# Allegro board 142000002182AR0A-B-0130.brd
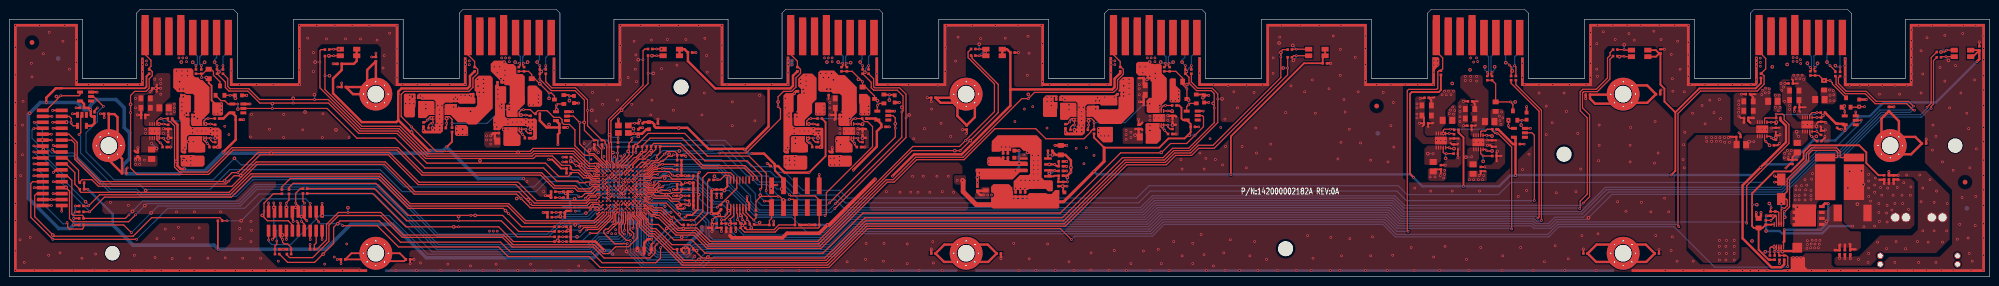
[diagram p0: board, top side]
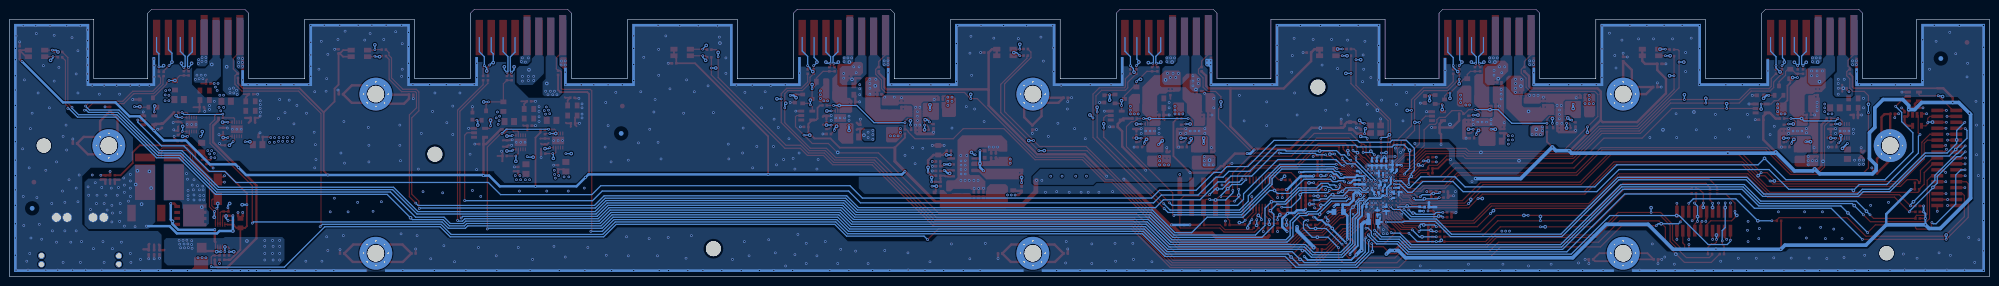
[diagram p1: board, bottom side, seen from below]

Outline 422.69 x 57.11 mm; copper layers: TOP, G2, V3, BOTTOM. Coordinates in mm from the lower left corner of the outline.
Outline path: 0,55 0,0 ; 0,55 15.6,55 ; 0,55 0,0 ; 0,55 15.6,55 ; 0,0 422.69,0 ; 0,0 422.69,0 ; 15.6,55 15.6,42.3 ; 15.6,55 15.6,42.3 ; 422.69,0 422.69,55 ; 422.69,0 422.69,55 ; 15.6,42.3 27.12,42.3 ; 15.6,42.3 27.12,42.3 ; 27.12,42.3 27.12,56.31 ; 27.12,42.3 27.12,56.31 ; 27.12,56.31 27.92,57.11 47.83,57.11 48.63,56.31 ; 48.63,56.31 48.63,42.3 ; 48.63,56.31 48.63,42.3 ; 48.63,42.3 60.61,42.3 ; 48.63,42.3 60.61,42.3 ; 60.61,42.3 60.61,55 ; 60.61,42.3 60.61,55 ; 60.61,55 84.04,55 ; 60.61,55 84.04,55 ; 84.04,55 84.04,42.3 ; 84.04,55 84.04,42.3 ; 84.04,42.3 96.02,42.3 ; 84.04,42.3 96.02,42.3 ; 96.02,42.3 96.02,56.31 ; 96.02,42.3 96.02,56.31 ; 96.02,56.31 96.82,57.11 116.73,57.11 117.53,56.31 ; 117.53,56.31 117.53,42.3 ; 117.53,56.31 117.53,42.3 ; 117.53,42.3 129.05,42.3 ; 117.53,42.3 129.05,42.3 ; 129.05,42.3 129.05,55 ; 129.05,42.3 129.05,55 ; 129.05,55 153.4,55 ; 129.05,55 153.4,55 ; 153.4,55 153.4,42.3 ; 153.4,55 153.4,42.3 ; 153.4,42.3 164.92,42.3 ; 153.4,42.3 164.92,42.3 ; 164.92,42.3 164.92,56.31 ; 164.92,42.3 164.92,56.31 ; 164.92,56.31 165.72,57.11 185.63,57.11 186.43,56.31 ; 186.43,56.31 186.43,42.3 ; 186.43,56.31 186.43,42.3 ; 186.43,42.3 198.41,42.3 ; 186.43,42.3 198.41,42.3 ; 198.41,42.3 198.41,55 ; 198.41,42.3 198.41,55 ; 198.41,55 221.84,55 ; 198.41,55 221.84,55 ; 221.84,55 221.84,42.3 ; 221.84,55 221.84,42.3 ; 221.84,42.3 233.82,42.3 ; 221.84,42.3 233.82,42.3 ; 233.82,42.3 233.82,56.31 ; 233.82,42.3 233.82,56.31 ; 233.82,56.31 234.62,57.11 254.53,57.11 255.33,56.31 ; 255.33,56.31 255.33,42.3 ; 255.33,56.31 255.33,42.3 ; 255.33,42.3 267.31,42.3 ; 255.33,42.3 267.31,42.3 ; 267.31,42.3 267.31,55 ; 267.31,42.3 267.31,55 ; 267.31,55 290.74,55 ; 267.31,55 290.74,55 ; 290.74,55 290.74,42.3 ; 290.74,55 290.74,42.3 ; 290.74,42.3 302.72,42.3 ; 290.74,42.3 302.72,42.3 ; 302.72,42.3 302.72,56.31 ; 302.72,42.3 302.72,56.31 ; 302.72,56.31 303.52,57.11 323.43,57.11 324.23,56.31 ; 324.23,56.31 324.23,42.3 ; 324.23,56.31 324.23,42.3 ; 324.23,42.3 336.21,42.3 ; 324.23,42.3 336.21,42.3 ; 336.21,42.3 336.21,55 ; 336.21,42.3 336.21,55 ; 336.21,55 359.64,55 ; 336.21,55 359.64,55 ; 359.64,55 359.64,42.3 ; 359.64,55 359.64,42.3 ; 359.64,42.3 371.62,42.3 ; 359.64,42.3 371.62,42.3 ; 371.62,42.3 371.62,56.31 ; 371.62,42.3 371.62,56.31 ; 371.62,56.31 372.42,57.11 392.33,57.11 393.13,56.31 ; 393.13,56.31 393.13,42.3 ; 393.13,56.31 393.13,42.3 ; 393.13,42.3 404.65,42.3 ; 393.13,42.3 404.65,42.3 ; 404.65,42.3 404.65,55 ; 404.65,42.3 404.65,55 ; 404.65,55 422.69,55 ; 404.65,55 422.69,55

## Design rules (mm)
constraint set DEFAULT: min track width 0.254
net group DIFF_FAN1: nets FAN1_IN_PWM FAN1_OUT_PWM
net group DIFF_FAN2: nets FAN2_IN_PWM FAN2_OUT_PWM
net group DIFF_FAN3: nets FAN3_IN_PWM FAN3_OUT_PWM
net group DIFF_FAN4: nets FAN4_IN_PWM FAN4_OUT_PWM
net group DIFF_FAN5: nets FAN5_IN_PWM FAN5_OUT_PWM
net group DIFF_FAN6: nets FAN6_IN_PWM FAN6_OUT_PWM
net group CLS_CLK_3W: nets 25MHZ_OUT 25MHZ_OUT_R CPLD_TCK FAN_SCL1_R FAN_SCL2_R I2C_ FAN_MNGMT_SCL I2C_FAN_BOT_SCL I2C_FAN_TOP_SCL I2C_SCL_LC1_R I2C_SCL_LC2_R I2C_SCL_MNGMT
net group CLS_GND: nets FAN1_S_GND FAN2_S_GND FAN3_S_GND FAN4_S_GND FAN5_S_GND FAN6_S_GND LGND_FAN12V LGND_VDD3P3
net group CLS_POWER: nets VCC_CL_FAN1F VCC_CL_FAN1R VCCA_FAN_CPLD
net group CLS_PWM: nets FAN1_PWM FAN2_PWM FAN3_PWM FAN4_PWM FAN5_PWM FAN6_PWM FAN7_PWM FAN8_PWM PWM_OUT1 PWM_OUT2 PWM_OUT3 PWM_OUT4 PWM_OUT5 PWM_OUT6 PWM_OUT7 PWM_OUT8

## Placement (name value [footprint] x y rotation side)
C1  0.1uF  [CC0402]  15.49 36.07 270 top
C2  0.1uF  [CC0402]  18.16 34.67 180 top
C3  1000pF/50V  [CC0402]  20.7 34.8 270 top
C4  1000pF/50V  [CC0402]  24.51 22.1 90 top
C5  0.1uF/16V  [CC0402]  27.43 26.16 0 top
C6  0.1uF/16V  [CC0402]  28.57 34.54 270 top
C7  22uF/16V  [CC0805]  29.08 38.1 270 top
C8  10uF/16V  [CC0805]  29.08 36.07 270 top
C9  1000pF  [CC0402]  30.99 40.26 90 top
C10  0.1uF/16V  [CC0402]  33.15 27.69 270 top
C11  0.1uF/16V  [CC0402]  33.91 32 180 top
C12  1000pF  [CC0402]  36.7 39.24 0 top
C13  0.1uF/16V  [CC0402]  37.47 26.16 0 top
C14  0.1uF/16V  [CC0402]  38.61 34.54 270 top
C15  22uF/16V  [CC0805]  39.12 38.1 270 top
C16  10uF/16V  [CC0805]  39.12 36.07 270 top
C17  0.1uF/16V  [CC0402]  43.18 27.69 270 top
C18  0.1uF/16V  [CC0402]  43.94 32 180 top
C19  0.1uF  [CC0402]  48.77 33.53 90 top
C20  0.1uF/16V  [CC0402]  70.48 45.47 270 top
C21  1000pF/50V  [CC0402]  71.25 3.68 270 top
C22  1000pF/50V  [CC0402]  71.37 40.51 270 top
C23  1000pF/50V  [CC0402]  78.23 46.48 180 top
C24  1000pF/50V  [CC0402]  85.09 3.68 90 top
C25  0.1uF/16V  [CC0402]  86.87 38.23 270 top
C26  0.1uF/16V  [CC0402]  88.39 32.51 180 top
C27  0.1uF/16V  [CC0402]  92.71 31.75 90 top
C28  0.1uF/16V  [CC0402]  95.25 37.08 180 top
C29  10uF/16V  [CC0805]  96.77 36.58 180 top
C30  22uF/16V  [CC0805]  98.81 36.58 180 top
C31  1000pF  [CC0402]  99.44 38.99 90 top
C32  0.1uF/16V  [CC0402]  103.63 31.11 0 top
C33  1000pF  [CC0402]  104.65 41.53 270 top
C34  0.1uF/16V  [CC0402]  105.92 36.45 270 top
C35  22uF/16V  [CC0805]  106.43 40.01 270 top
C36  10uF/16V  [CC0805]  106.43 37.97 270 top
C37  0.1uF/16V  [CC0402]  110.49 29.59 270 top
C38  0.1uF/16V  [CC0402]  111.25 33.91 180 top
C39  0.1uF  [CC0402]  117.86 31.88 90 top
C40  0.1uF  [CC0402]  134.24 30.99 180 top
C41  0.1uF  [CC0402]  138.43 32.26 180 top
C42  0.1uF/16V  [CC0402]  145.29 47.88 90 top
C43  0.1uF  [CC0402]  150.98 18.14 0 top
C44  0.1uF  [CC0402]  151.99 18.14 0 top
C45  0.1uF  [CC0402]  162.94 23.62 90 top
C46  0.1uF  [CC0402]  166.12 26.16 0 top
C47  0.1uF/16V  [CC0402]  167.26 34.54 270 top
C48  22uF/16V  [CC0805]  167.77 38.1 270 top
C49  10uF/16V  [CC0805]  167.77 36.07 270 top
C50  1000pF  [CC0402]  168.78 39.62 90 top
C51  0.1uF/16V  [CC0402]  171.83 27.69 270 top
C52  0.1uF/16V  [CC0402]  172.59 32 180 top
C53  1000pF  [CC0402]  174.88 39.24 0 top
C54  0.1uF/16V  [CC0402]  175.64 26.16 0 top
C55  0.1uF/16V  [CC0402]  176.78 34.54 270 top
C56  22uF/16V  [CC0805]  177.29 38.1 270 top
C57  10uF/16V  [CC0805]  177.29 36.07 270 top
C58  0.1uF/16V  [CC0402]  181.36 27.69 270 top
C59  0.1uF/16V  [CC0402]  182.12 32 180 top
C60  0.1uF  [CC0402]  186.56 32 90 top
C61  1000pF/50V  [CC0402]  197.23 38.23 270 top
C62  1000pF/50V  [CC0402]  197.23 4.95 270 top
C63  1000pF/50V  [CC0402]  204.34 31.88 0 top
C64  2200pF/50V  [CC0402]  206.63 18.8 0 top
C65  22uF/16V  [CC1206]  210.46 26.14 180 top
C66  1000pF/50V  [CC0402]  211.2 4.95 90 top
C67  1nF/50V  [CC0402]  212.12 25.88 180 top
C68  0.1uF/16V  [CC0402]  213.13 25.88 180 top
C69  0.1uF/16V  [CC0402]  214.12 47.88 90 top
C70  0.1uF/50V  [CC0603]  214.5 26.16 180 top
C71  1uF/6.3V  [CC0402]  214.78 17.55 180 top
C72  0.1uF/16V  [CC0402]  215.8 17.55 180 top
C73  1uF/6.3V  [CC0402]  216.81 17.55 180 top
C74  22uF/6.3V  [CC0805]  218.34 18.31 180 top
C75  22uF/6.3V  [CC0805]  220.37 18.31 180 top
C76  8200pF/16V  [CC0402]  222.15 26.9 90 top
C77  10uF/6.3V  [CC0603]  222.15 17.93 180 top
C78  0.1uF/16V  [CC0402]  223.9 37.85 270 top
C79  22pF/50V  [CC0402]  223.93 19.79 180 top
C80  10pF  [CC0402]  224.43 23.6 90 top
C81  0.47uF/6.3V  [CC0402]  224.43 22.58 90 top
C82  0.1uF/16V  [CC0402]  225.43 32.13 180 top
C83  0.1uF/16V  [CC0402]  229.74 31.37 90 top
C84  0.1uF/16V  [CC0402]  232.28 36.7 180 top
C85  10uF/16V  [CC0805]  233.81 36.2 180 top
C86  22uF/16V  [CC0805]  235.84 36.2 180 top
C87  1000pF  [CC0402]  236.98 38.99 90 top
C88  0.1uF/16V  [CC0402]  241.05 32 0 top
C89  1000pF  [CC0402]  242.57 42.42 270 top
C90  0.1uF/16V  [CC0402]  242.57 37.34 270 top
C91  22uF/16V  [CC0805]  243.46 40.89 270 top
C92  10uF/16V  [CC0805]  243.46 38.86 270 top
C93  0.1uF/16V  [CC0402]  247.78 30.48 270 top
C94  0.1uF/16V  [CC0402]  248.28 34.8 180 top
C95  0.1uF  [CC0402]  252.6 32 90 top
C96  0.1uF/16V  [CC0402]  280.8 45.59 90 top
C97  0.1uF/16V  [CC0402]  302.39 32.77 270 top
C98  1000pF  [CC0402]  302.51 38.23 90 top
C99  10uF/16V  [CC0805]  302.51 36.58 270 top
C100  22uF/16V  [CC0805]  302.51 34.42 270 top
C101  0.1uF  [CC0402]  305.56 23.37 0 top
C102  0.1uF/16V  [CC0402]  308.36 29.97 180 top
C103  0.1uF/16V  [CC0402]  308.74 26.29 270 top
C104  0.1uF/16V  [CC0402]  311.66 32.26 270 top
C105  1000pF  [CC0402]  311.79 37.47 270 top
C106  10uF/16V  [CC0805]  311.79 35.81 270 top
C107  22uF/16V  [CC0805]  311.79 33.78 270 top
C108  0.1uF/16V  [CC0402]  314.07 22.99 0 top
C109  0.1uF/16V  [CC0402]  316.48 29.59 180 top
C110  0.1uF/16V  [CC0402]  316.99 25.78 270 top
C111  0.1uF  [CC0402]  321.94 28.32 90 top
C112  1000pF/50V  [CC0402]  336.42 4.95 270 top
C113  1000pF/50V  [CC0402]  336.93 38.86 270 top
C114  1000pF/50V  [CC0402]  351.66 4.95 90 top
C115  1000pF/50V  [CC0402]  351.92 38.99 90 top
C116  0.1uF/16V  [CC0402]  352.43 48.13 180 top
C117  0.1uF/16V  [CC0402]  369.06 29.84 270 top
C118  0.1uF/16V  [CC0402]  370.71 33.91 270 top
C119  1000pF  [CC0402]  371.09 38.99 90 top
C120  22uF/16V  [CC0805]  371.22 37.47 270 top
C121  10uF/16V  [CC0805]  371.22 35.43 270 top
C122  6800pF  [CC0402]  375.79 4.06 0 top
C123  0.1uF/16V  [CC0402]  376.17 28.07 270 top
C124  0.1uF/16V  [CC0402]  377.06 32.26 180 top
C125  0.1uF/16V  [CC0402]  377.82 4.06 0 top
C126  1000pF  [CC0402]  380.24 41.27 270 top
C127  0.1uF/16V  [CC0402]  380.62 24.51 180 top
C128  10uF/16V  [CC0805]  381 39.75 270 top
C129  22uF/16V  [CC0805]  381 37.72 270 top
C130  0.1uF/16V  [CC0402]  381.63 36.2 270 top
C131  0.1uF/16V  [CC0402]  386.33 28.96 270 top
C132  0.1uF/16V  [CC0402]  386.71 33.53 180 top
C133  0.1uF  [CC0402]  390.14 32.26 0 top
C134  1000pF/50V  [CC0402]  390.65 5.21 0 top
C135  0.1uF/16V  [CC0402]  391.8 5.21 0 top
C136  1000pF/50V  [CC0402]  392.94 5.21 0 top
C137  1nF/50V  [CC0402]  400.18 21.21 180 top
C138  1000pF/50V  [CC0402]  401.19 35.81 180 top
C139  1nF/50V  [CC0402]  401.19 21.21 180 top
C140  0.1uF/16V  [CC0402]  402.21 21.21 180 top
C141  1000pF/50V  [CC0402]  408.69 28.45 90 top
C142  0.1uF/16V  [CC0402]  420.5 48.77 180 top
C143  0.1uF  [CC0402]  126.11 18.54 0 bottom
C144  0.1uF  [CC0402]  127 23.88 90 bottom
C145  0.1uF  [CC0402]  127 22.86 90 bottom
C146  0.1uF  [CC0402]  127.13 17.27 180 bottom
C147  0.1uF  [CC0402]  128.27 20.57 270 bottom
C148  0.1uF  [CC0402]  128.78 14.48 180 bottom
C149  0.1uF  [CC0402]  128.8 24.21 0 bottom
C150  0.1uF  [CC0402]  129.54 19.61 90 bottom
C151  0.1uF  [CC0402]  129.54 17.78 0 bottom
C152  0.1uF  [CC0402]  129.82 24.21 0 bottom
C153  0.1uF  [CC0402]  129.92 22.1 90 bottom
C154  0.1uF  [CC0402]  130.68 13.72 180 bottom
C155  0.1uF  [CC0402]  130.84 24.21 0 bottom
C156  0.1uF  [CC0402]  130.94 18.03 90 bottom
C157  22uF  [CC0805]  131.57 11.68 90 bottom
C158  0.1uF  [CC0402]  131.85 24.21 0 bottom
C159  0.1uF  [CC0402]  133.48 14.86 90 bottom
C160  0.1uF  [CC0402]  134.49 20.19 0 bottom
C161  0.1uF  [CC0402]  135 22.1 0 bottom
C162  0.1uF  [CC0402]  135.51 20.19 0 bottom
C163  0.1uF  [CC0402]  138.56 15.37 270 bottom
C164  22uF  [CC0805]  138.94 13.84 270 bottom
CONN1  LCB25-G3424S01C-04  [CONNM_1D27X4D05_2X17SP_36D09W]  9.15 25.36 270 top
CONN2  LCB25-G2024S01C-04  [CONNM_1D27X4D05_2X10SP_27D2W]  61.04 11.85 0 top
CONN3  PHED-SS010G1ABONE-B140  [CONNM_2D54X4D65_2X5SP_12D7W5L]  167.78 17.08 180 top
CONN4  -  [CONN_2D3_4DP_18D2W12D3L_PIP]  407.59 12.65 180 top
D1  SS1040  [SOD123_3D28_2SP_AC]  208.41 20.07 0 top
D2  P4SMAJ58A  [DIOZENER_2SP_2D6WX4D5L_AC]  378.21 18.67 180 top
D3  1SMA4744  [DO214AC_3D73_2SP_2D7W4D3L2D44H]  381.63 4.32 90 top
H1  *SCREW_8_1  [MTH_276C138D_8DP_OSP]  21.23 28 0 top
H2  *SCREW_8_1  [MTH_276C138D_8DP_OSP]  78.22 39 0 top
H3  *SCREW_8_1  [MTH_276C138D_8DP_OSP]  78.22 5 0 top
H4  *SCREW_8_1  [MTH_276C138D_8DP_OSP]  204.22 39 0 top
H5  *SCREW_8_1  [MTH_276C138D_8DP_OSP]  204.22 5 0 top
H6  *SCREW_8_1  [MTH_276C138D_8DP_OSP]  344.46 39 0 top
H7  *SCREW_8_1  [MTH_276C138D_8DP_OSP]  344.46 5 0 top
H8  *SCREW_8_1  [MTH_276C138D_8DP_OSP]  401.47 28 0 top
L1  100MHz/5A  [LC0805]  30.35 26.16 180 top
L2  100MHz/5A  [LC0805]  33.02 36.07 270 top
L3  100MHz/5A  [LC0805]  40.39 26.16 180 top
L4  100MHz/5A  [LC0805]  43.05 36.07 270 top
L5  100MHz/5A  [LC0805]  86.87 35.31 90 top
L6  100MHz/5A  [LC0805]  96.77 32.64 180 top
L7  100MHz/5A  [LC0805]  105.16 28.96 90 top
L8  100MHz/5A  [LC0805]  110.36 37.97 270 top
L9  100MHz  [LC0603]  136.27 5.84 90 top
L10  100MHz  [LC0603]  136.53 32.26 180 top
L11  100MHz/5A  [LC0805]  169.04 26.16 180 top
L12  100MHz/5A  [LC0805]  171.7 36.07 270 top
L13  100MHz/5A  [LC0805]  178.56 26.16 180 top
L14  100MHz/5A  [LC0805]  181.23 36.07 270 top
L15  1.5uH/4.5A  [CHOKE_3D7_2SP_4W4D5L2H]  211.86 20.29 270 top
L16  100MHz/5A  [LC0805]  223.9 35.18 90 top
L17  100MHz/5A  [LC0805]  233.81 32.26 180 top
L18  100MHz/5A  [LC0805]  242.32 29.84 90 top
L19  100MHz/5A  [LC0805]  247.4 38.86 270 top
L20  100MHz/5A  [LC0805]  303.91 23.5 180 top
L21  100MHz/5A  [LC0805]  306.96 33.4 270 top
L22  100MHz/5A  [LC0805]  312.42 22.99 180 top
L23  100MHz/5A  [LC0805]  315.98 33.15 270 top
L24  100MHz/5A  [LC0805]  369.7 28.19 90 top
L25  100MHz/5A  [LC0805]  376.43 37.47 270 top
L26  100MHz/5A  [LC0805]  381.63 27.56 180 top
L27  100MHz/5A  [LC0805]  386.46 37.85 270 top
LED1  -  [LED_1D4X3D5_4SP_2D7W3D2L1D1H_AC]  72.39 47.9 0 top
LED2  -  [LED_1D4X3D5_4SP_2D7W3D2L1D1H_AC]  141.29 47.9 0 top
LED3  -  [LED_1D4X3D5_4SP_2D7W3D2L1D1H_AC]  210.19 47.9 0 top
LED4  -  [LED_1D4X3D5_4SP_2D7W3D2L1D1H_AC]  279.09 47.9 0 top
LED5  -  [LED_1D4X3D5_4SP_2D7W3D2L1D1H_AC]  347.99 47.7 0 top
LED6  -  [LED_1D4X3D5_4SP_2D7W3D2L1D1H_AC]  416.89 47.7 0 top
NOREF  -  []  141.29 47.7 0 top
NOREF#2  -  [unnamed#2]  4.83 50.04 0 top
NOREF#3  -  []  60.61 55 0 top
NOREF#4  -  []  290.74 55 0 top
NOREF#5  -  []  402.54 12.65 0 top
NOREF#6  -  []  347.99 47.7 0 top
NOREF#7  -  []  0 0 0 top
NOREF#8  -  []  117.53 56.31 0 top
NOREF#9  -  []  9.15 25.36 0 top
NOREF#10  -  []  21.23 28 0 top
NOREF#11  -  []  401.47 28 0 top
NOREF#12  -  []  302.72 56.31 0 top
NOREF#13  -  []  0 0 0 top
NOREF#14  -  []  279.09 47.7 0 top
NOREF#15  -  [unnamed#2]  417.45 20.19 0 top
NOREF#16  -  []  204.22 39 0 top
NOREF#17  -  []  344.46 39 0 top
NOREF#18  -  []  22 5 0 top
NOREF#19  -  []  422.69 55 0 top
NOREF#20  -  [unnamed#2]  272.42 5.97 0 top
NOREF#21  -  []  221.84 55 0 top
NOREF#22  -  []  72.39 47.7 0 top
NOREF#23  -  []  78.22 39 0 top
NOREF#24  -  []  324.23 56.31 0 top
NOREF#25  -  []  422.69 0 0 top
NOREF#26  -  []  415.34 28 0 top
NOREF#27  -  []  267.31 55 0 top
NOREF#28  -  []  270.76 23.37 0 top
NOREF#29  -  []  255.33 56.31 0 top
NOREF#30  -  []  325.75 -37.8 0 top
NOREF#31  -  []  -35.56 -29.21 0 top
NOREF#32  -  []  210.19 47.7 0 top
NOREF#33  -  []  27.12 56.31 0 top
NOREF#34  -  []  96.02 56.31 0 top
NOREF#35  -  []  164.92 56.31 0 top
NOREF#36  -  []  393.13 56.31 0 top
NOREF#37  -  []  72.39 47.7 0 top
NOREF#38  -  []  186.43 56.31 0 top
NOREF#39  -  []  153.4 55 0 top
NOREF#40  -  []  336.21 55 0 top
NOREF#41  -  []  22 5 0 top
NOREF#42  -  []  404.65 42.3 0 top
NOREF#43  -  []  84.04 55 0 top
NOREF#44  -  []  233.82 56.31 0 top
NOREF#45  -  []  198.41 55 0 top
NOREF#46  -  []  61.04 11.85 0 top
NOREF#47  -  []  129.05 55 0 top
NOREF#48  -  []  416.89 47.7 0 top
NOREF#49  -  [unnamed#2]  291.85 36.45 0 top
NOREF#50  -  []  0 0 0 top
NOREF#51  -  [unnamed#2]  331.85 26.16 0 top
NOREF#52  -  []  404.65 55 0 top
NOREF#53  -  [unnamed#2]  143.38 40.51 0 top
NOREF#54  -  []  359.64 55 0 top
NOREF#55  -  []  61.04 11.85 0 top
NOREF#56  -  []  422.69 55 0 top
NOREF#57  -  []  0 0 0 top
NOREF#58  -  []  15.6 55 0 top
NOREF#59  -  []  21.23 28 0 top
NOREF#60  -  [unnamed#2]  415.34 28 0 top
NOREF#61  -  []  48.63 56.31 0 top
NOREF#62  -  []  78.22 39 0 top
NOREF#63  -  []  511.81 -43.81 0 top
NOREF#64  -  []  392.33 57.11 0 top
NOREF#65  -  []  9.15 25.36 0 top
NOREF#66  -  []  402.54 12.65 0 top
NOREF#67  -  []  371.62 56.31 0 top
NOREF#68  -  [unnamed#2]  22 5 0 top
NOREF#69  -  [unnamed#2]  417.83 14.61 180 bottom
NOREF#70  -  [unnamed#2]  292.1 30.61 180 bottom
NOREF#71  -  [unnamed#2]  10.41 46.61 180 bottom
OSC1  25MHz  [OSC_1D6X2D12_4SP_2D5W3D2L1DH]  131.06 31.5 180 top
Q1  SN74LVC1G04DBVR  [SOT23_D95X2D35_5SP_1D6W2D9L]  15.49 33.4 180 top
Q2  SN74LVC1G04DBVR  [SOT23_D95X2D35_5SP_1D6W2D9L]  16.26 38.48 90 top
Q3  N-CH  [SOT23_1D9X2D_3SP_1D3W3L_GSD]  44.96 39.75 0 top
Q4  SN74LVC1G04DBVR  [SOT23_D95X2D35_5SP_1D6W2D9L]  48.77 35.94 90 top
Q5  N-CH  [SOT23_1D9X2D_3SP_1D3W3L_GSD]  117.35 37.85 90 top
Q6  SN74LVC1G04DBVR  [SOT23_D95X2D35_5SP_1D6W2D9L]  117.86 34.29 90 top
Q7  N-CH  [SOT23_1D9X2D_3SP_1D3W3L_GSD]  185.67 37.97 90 top
Q8  SN74LVC1G04DBVR  [SOT23_D95X2D35_5SP_1D6W2D9L]  186.44 34.42 90 top
Q9  N-CH  [SOT23_1D9X2D_3SP_1D3W3L_GSD]  252.35 37.97 90 top
Q10  SN74LVC1G04DBVR  [SOT23_D95X2D35_5SP_1D6W2D9L]  252.48 34.42 90 top
Q11  N-CH  [SOT23_1D9X2D_3SP_1D3W3L_GSD]  320.93 34.42 0 top
Q12  SN74LVC1G04DBVR  [SOT23_D95X2D35_5SP_1D6W2D9L]  322.33 30.73 90 top
Q13  N-CH  [SOT23_1D9X2D_3SP_1D3W3L_GSD]  392.05 37.21 0 top
Q14  SN74LVC1G04DBVR  [SOT23_D95X2D35_5SP_1D6W2D9L]  392.94 33.4 90 top
R1  4.7Kohm  [RC0402]  15.37 15.11 270 top
R2  4.7Kohm  [RC0402]  15.37 13.84 270 top
R3  4.7Kohm  [RC0402]  15.37 12.45 270 top
R4  4.7Kohm  [RC0402]  15.37 11.05 270 top
R5  4.7Kohm  [RC0402]  15.49 20.07 90 top
R6  4.7Kohm  [RC0402]  15.49 18.67 90 top
R7  10Kohm  [RC0402]  29.84 43.81 180 top
R8  2.8Kohm  [RC0402]  33.91 29.21 0 top
R9  4.7Kohm  [RC0402]  34.29 33.78 270 top
R10  0ohm  [RC0402]  39.83 43.81 0 top
R11  0ohm  [RC0402]  40.97 43.81 0 top
R12  7.5Kohm  [RC0805]  42.55 43.31 0 top
R13  2.8Kohm  [RC0402]  43.94 29.21 0 top
R14  0ohm  [RC0402]  44.32 43.81 180 top
R15  4.7Kohm  [RC0402]  44.32 33.78 270 top
R16  4.7Kohm  [RC0402]  44.96 11.94 270 top
R17  0ohm  [RC0402]  45.59 43.81 0 top
R18  0ohm  [RC0603]  48.9 38.73 270 top
R19  4.7Kohm  [RC0402]  57.15 5.84 90 top
R20  0ohm  [RC0402]  57.15 4.83 90 top
R21  0ohm  [RC0402]  58.17 18.16 180 top
R22  0ohm  [RC0402]  59.69 18.16 180 top
R23  4.7Kohm  [RC0402]  59.69 5.84 270 top
R24  0ohm  [RC0402]  59.69 4.83 270 top
R25  0ohm  [RC0402]  63.12 18.8 90 top
R26  0ohm  [RC0402]  63.12 17.78 90 top
R27  10Kohm  [RC0402]  64.64 5.84 90 top
R28  110ohm  [RC0402]  67.82 48.51 90 top
R29  110ohm  [RC0402]  67.82 47.12 90 top
R30  2.8Kohm  [RC0402]  89.92 31.75 270 top
R31  4.7Kohm  [RC0402]  94.49 31.37 180 top
R32  10Kohm  [RC0402]  99.31 44.32 180 top
R33  0ohm  [RC0402]  108.73 44.32 0 top
R34  0ohm  [RC0402]  109.87 44.32 0 top
R35  2.8Kohm  [RC0402]  111.25 31.11 0 top
R36  7.5Kohm  [RC0805]  111.51 41.27 0 top
R37  4.7Kohm  [RC0402]  112.78 34.8 270 top
R38  0ohm  [RC0402]  113.22 43.81 180 top
R39  0ohm  [RC0402]  114.49 43.81 0 top
R40  4.7Kohm  [RC0402]  115.32 13.72 90 top
R41  4.7Kohm  [RC0402]  115.32 12.7 90 top
R42  4.7Kohm  [RC0402]  116.08 18.16 90 top
R43  4.7Kohm  [RC0402]  116.08 16.89 90 top
R44  33ohm  [RC0402]  116.84 10.67 270 top
R45  33ohm  [RC0402]  116.84 9.65 270 top
R46  33ohm  [RC0402]  116.84 8.51 270 top
R47  33ohm  [RC0402]  116.84 7.49 270 top
R48  10Kohm  [RC0402]  118.11 13.72 90 top
R49  10Kohm  [RC0402]  118.11 12.7 90 top
R50  10Kohm  [RC0402]  118.75 18.16 90 top
R51  10Kohm  [RC0402]  118.75 16.89 90 top
R52  33ohm  [RC0402]  119.38 25.53 270 top
R53  33ohm  [RC0402]  119.38 24.51 270 top
R54  4.7Kohm  [RC0402]  119.38 23.11 270 top
R55  4.7Kohm  [RC0402]  119.38 22.1 270 top
R56  4.7Kohm  [RC0402]  119.38 10.67 90 top
R57  4.7Kohm  [RC0402]  119.38 9.65 90 top
R58  4.7Kohm  [RC0402]  119.38 8.51 90 top
R59  4.7Kohm  [RC0402]  119.38 7.49 90 top
R60  0ohm  [RC0603]  120.52 37.85 180 top
R61  4.7Kohm  [RC0402]  124.84 28.7 0 top
R62  4.7Kohm  [RC0402]  126.49 28.7 0 top
R63  33ohm  [RC0402]  129.92 28.19 180 top
R64  0ohm  [RC0402]  132.72 27.81 90 top
R65  0ohm  [RC0402]  134.62 27.81 90 top
R66  4.7Kohm  [RC0402]  134.75 32.77 270 top
R67  0ohm  [RC0402]  136.53 27.81 90 top
R68  110ohm  [RC0402]  136.78 48.64 90 top
R69  110ohm  [RC0402]  136.78 47.24 90 top
R70  0ohm  [RC0402]  138.43 27.81 90 top
R71  10Kohm  [RC0402]  142.88 15.24 270 top
R72  10Kohm  [RC0402]  143 25.91 270 top
R73  4.7Kohm  [RC0402]  143 24.89 90 top
R74  4.7Kohm  [RC0402]  143 23.88 90 top
R75  4.7Kohm  [RC0402]  143 22.86 90 top
R76  10Kohm  [RC0402]  143 21.56 90 top
R77  10Kohm  [RC0402]  143 19.68 270 top
R78  10Kohm  [RC0402]  143 18.67 270 top
R79  10Kohm  [RC0402]  143 17.27 270 top
R80  4.7Kohm  [RC0402]  143 5.84 90 top
R81  33ohm  [RC0402]  144.4 11.05 90 top
R82  10Kohm  [RC0402]  145.54 21.56 270 top
R83  10Kohm  [RC0402]  145.54 20.07 90 top
R84  10Kohm  [RC0402]  145.54 18.67 90 top
R85  10Kohm  [RC0402]  145.54 17.27 90 top
R86  10Kohm  [RC0402]  145.54 16.26 90 top
R87  10Kohm  [RC0402]  145.54 15.24 90 top
R88  4.7Kohm  [RC0402]  145.54 5.84 270 top
R89  33ohm  [RC0402]  149.83 20.68 90 top
R90  4.7Kohm  [RC0402]  149.96 10.9 0 top
R91  10Kohm  [RC0402]  150.98 10.9 0 top
R92  1Kohm  [RC0402]  151.89 14.86 0 top
R93  10Kohm  [RC0402]  151.99 10.9 0 top
R94  4.7Kohm  [RC0402]  153.01 10.9 0 top
R95  4.7Kohm  [RC0402]  154.03 10.9 0 top
R96  10Kohm  [RC0402]  155.04 10.9 0 top
R97  0ohm  [RC0402]  156.06 10.9 0 top
R98  0ohm  [RC0402]  157.07 10.9 0 top
R99  0ohm  [RC0402]  158.5 11.18 90 top
R100  0ohm  [RC0402]  159.36 13.69 180 top
R101  1Kohm  [RC0402]  162.69 11.05 270 top
R102  10Kohm  [RC0402]  168.15 11.05 90 top
R103  10Kohm  [RC0402]  168.21 44.32 180 top
R104  10Kohm  [RC0402]  172.47 11.05 270 top
R105  2.8Kohm  [RC0402]  172.59 29.21 0 top
R106  4.7Kohm  [RC0402]  172.97 33.78 270 top
R107  0ohm  [RC0402]  177.63 44.32 0 top
R108  0ohm  [RC0402]  178.77 44.32 0 top
R109  7.5Kohm  [RC0805]  182.12 39.5 0 top
R110  2.8Kohm  [RC0402]  182.12 29.21 0 top
R111  0ohm  [RC0402]  182.12 43.81 180 top
R112  4.7Kohm  [RC0402]  182.5 33.78 270 top
R113  0ohm  [RC0402]  183.39 43.81 0 top
R114  0ohm  [RC0603]  188.98 37.97 180 top
R115  110ohm  [RC0402]  205.74 48.64 90 top
R116  110ohm  [RC0402]  205.74 47.24 90 top
R117  2.2ohm  [RC0402]  206.63 21.34 180 top
R118  0ohm  [RC0805]  224.43 27.03 0 top
R119  10Kohm  [RC0402]  224.43 24.61 90 top
R120  10Kohm  [RC0402]  224.43 21.56 90 top
R121  49.9ohm  [RC0603]  224.43 18.01 270 top
R122  33.2Kohm  [RC0402]  224.94 19.79 0 top
R123  2.8Kohm  [RC0402]  226.95 31.37 270 top
R124  4.7Kohm  [RC0402]  231.52 30.99 180 top
R125  10Kohm  [RC0402]  237.11 44.32 180 top
R126  0ohm  [RC0402]  246.53 44.32 0 top
R127  0ohm  [RC0402]  247.67 44.32 0 top
R128  2.8Kohm  [RC0402]  248.28 32 0 top
R129  4.7Kohm  [RC0402]  248.67 36.58 270 top
R130  7.5Kohm  [RC0805]  249.43 41.66 270 top
R131  0ohm  [RC0402]  251.02 43.81 180 top
R132  0ohm  [RC0402]  252.29 43.81 0 top
R133  0ohm  [RC0603]  255.02 37.97 180 top
R134  110ohm  [RC0402]  273.3 48.51 90 top
R135  110ohm  [RC0402]  273.3 46.86 90 top
R136  10Kohm  [RC0402]  305.56 43.56 180 top
R137  2.8Kohm  [RC0402]  308.36 27.81 0 top
R138  4.7Kohm  [RC0402]  308.86 31.37 270 top
R139  0ohm  [RC0402]  315.47 42.42 0 top
R140  0ohm  [RC0402]  316.48 42.42 0 top
R141  2.8Kohm  [RC0402]  316.48 27.3 0 top
R142  4.7Kohm  [RC0402]  316.99 31.5 270 top
R143  7.5Kohm  [RC0805]  317.25 36.32 0 top
R144  0ohm  [RC0402]  320.55 42.42 180 top
R145  0ohm  [RC0402]  321.56 42.42 0 top
R146  0ohm  [RC0603]  323.85 34.29 0 top
R147  110ohm  [RC0402]  342.77 48.51 90 top
R148  110ohm  [RC0402]  342.77 47.12 90 top
R149  0ohm  [RC0805]  373.38 11.43 180 top
R150  10Kohm  [RC0402]  373.89 42.93 180 top
R151  4.64Kohm  [RC0402]  374.9 11.56 180 top
R152  23.7Kohm  [RC0402]  375.92 13.46 0 top
R153  8.87Kohm  [RC0402]  376.81 4.06 180 top
R154  3.24Kohm  [RC0402]  376.94 13.46 180 top
R155  2.8Kohm  [RC0402]  377.06 29.72 0 top
R156  4.7Kohm  [RC0402]  377.57 33.91 270 top
R157  4.7Kohm  [RC0402]  378.84 4.06 0 top
R158  0ohm  [RC0402]  384.43 43.43 0 top
R159  0ohm  [RC0402]  385.44 43.43 0 top
R160  2.8Kohm  [RC0402]  386.71 30.73 0 top
R161  4.7Kohm  [RC0402]  387.1 35.05 270 top
R162  7.5Kohm  [RC0805]  387.35 40.89 0 top
R163  0ohm  [RC0402]  389.76 43.31 180 top
R164  0.001ohm  [RC_6D15_2SP_9D14W9D4L]  390.65 21.34 0 top
R165  0ohm  [RC0402]  390.78 43.31 0 top
R166  0.001ohm  [RC2512]  393.45 13.59 90 top
R167  0ohm  [RC0603]  394.84 37.08 0 top
R168  110ohm  [RC0402]  411.86 48.01 90 top
R169  110ohm  [RC0402]  411.86 46.86 90 top
R170  4.7Kohm  [RC0402]  120.14 14.86 270 bottom
R171  10Kohm  [RC0402]  121.67 14.48 180 bottom
U1  SY6875ADBC  [DFN_D5X3D_10SP_3WL1H_G1]  30.99 31.11 0 top
U2  Golden Finger  [GOLD_FINGER_2D54_8X2SP]  46.76 51.09 0 top
U3  SY6875ADBC  [DFN_D5X3D_10SP_3WL1H_G1]  41.02 31.11 0 top
U4  SY6875ADBC  [DFN_D5X3D_10SP_3WL1H_G1]  91.82 34.67 270 top
U5  Golden Finger  [GOLD_FINGER_2D54_8X2SP]  115.66 51.09 0 top
U6  SY6875ADBC  [DFN_D5X3D_10SP_3WL1H_G1]  108.33 33.02 0 top
U7  10M04SCU169C8G  [BGA_D8_16C_169SP_11WL1D55H]  130.68 18.54 270 top
U8  PCA9534PW  [TSSOP_D65X5D8_16SP_5L]  155.59 17.71 90 top
U9  SY6875ADBC  [DFN_D5X3D_10SP_3WL1H_G1]  169.67 31.11 0 top
U10  Golden Finger  [GOLD_FINGER_2D54_8X2SP]  184.56 51.09 0 top
U11  SY6875ADBC  [DFN_D5X3D_10SP_3WL1H_G1]  179.2 31.11 0 top
U12  TPS54329DDAR  [SOP_1D27X5D165_8SP_3D9W_G95X130]  219.1 23.34 0 top
U13  SY6875ADBC  [DFN_D5X3D_10SP_3WL1H_G1]  228.85 34.29 270 top
U14  Golden Finger  [GOLD_FINGER_2D54_8X2SP]  253.46 51.09 0 top
U15  SY6875ADBC  [DFN_D5X3D_10SP_3WL1H_G1]  245.36 33.91 0 top
U16  SY6875ADBC  [DFN_D5X3D_10SP_3WL1H_G1]  305.56 29.08 0 top
U17  Golden Finger  [GOLD_FINGER_2D54_8X2SP]  322.37 51.09 0 top
U18  SY6875ADBC  [DFN_D5X3D_10SP_3WL1H_G1]  313.56 28.7 0 top
U19  SY6875ADBC  [DFN_D5X3D_10SP_3WL1H_G1]  374.14 31.49 0 top
U20  LM5069MM-2/NOPB  [MSOP_D5X4D8_10SP_3WL1D09H]  377.7 8.76 180 top
U21  Golden Finger  [GOLD_FINGER_2D54_8X2SP]  391.27 51.1 0 top
U22  SY6875ADBC  [DFN_D5X3D_10SP_3WL1H_G1]  383.79 32.51 0 top
U23  N-CH  [SO8_3D75X1D27_5SP]  384.05 13.08 0 top

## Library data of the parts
C1-C164 = C_NP
CONN1 = PIN HEADER_MALE_17PX2R
CONN2 = PIN HEADER_MALE_10PX2R
CONN3 = PINSTICK_MALE_5PX2R
CONN4 = CONN_POWER_4P_G4
D1 = DIODE1_1
D2 = TVS1_1
D3 = ZENER1_1
H1-H8 = SCREW_8_1
L1-L8 L11-L14 L16-L27 = BEAD
L9 L10 = BEAD: room: 8
L15 = POWER CHOKE
LED1-LED6 = LED2_1
OSC1 = OSC_10
Q1 Q2 Q4 Q6 Q8 Q10 Q12 Q14 = TTL_TI_SN74LVC1G04
Q3 Q5 Q7 Q9 Q11 Q13 = NMOS1_1
R1-R26 R28-R39 R44-R47 R52-R65 R67-R71 R73-R90 R94 R95 R97-R100 R102-R118 R120-R163 R165-R169 = R: tolerance: 1%
R27 R40-R43 R66 R72 R170 = R: tolerance: 1%; room: U83
R48-R51 R91 R93 R96 R171 = R
R92 = R: room: 1
R101 = R: tolerance: 1%; room: 41
R119 = R: room: 71
R164 = R_4P: tolerance: 1%
U1 U3 U4 U6 U9 U11 U13 U15 U16 U18 U19 U22 = MONITOR_CUR_SILERGY_SY6875
U2 U5 U10 U14 U17 U21 = Golden Finger
U7 = FPGA_ALTERA_10M04SCU169
U8 = I2C_NXP_PCA9534
U12 = DC_DC_TI_TPS54329
U20 = HOT SWAP_NS_LM5069
U23 = NMOS1_6

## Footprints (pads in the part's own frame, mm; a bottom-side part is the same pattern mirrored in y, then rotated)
BGA_D8_16C_169SP_11WL1D55H
  round 0.508 smd: (-6.5,-6.5) (6.5,6.5)
  round 0.406 smd: A1(-4.8,4.8) A2(-4,4.8) A3(-3.2,4.8) A4(-2.4,4.8) A5(-1.6,4.8) A6(-0.8,4.8) A7(0,4.8) A8(0.8,4.8) A9(1.6,4.8) A10(2.4,4.8) A11(3.2,4.8) A12(4,4.8) A13(4.8,4.8) B1(-4.8,4) B2(-4,4) B3(-3.2,4) B4(-2.4,4) B5(-1.6,4) B6(-0.8,4) B7(0,4) B8(0.8,4) B9(1.6,4) B10(2.4,4) B11(3.2,4) B12(4,4) B13(4.8,4) C1(-4.8,3.2) C2(-4,3.2) C3(-3.2,3.2) C4(-2.4,3.2) C5(-1.6,3.2) C6(-0.8,3.2) C7(0,3.2) C8(0.8,3.2) C9(1.6,3.2) C10(2.4,3.2) C11(3.2,3.2) C12(4,3.2) C13(4.8,3.2) D1(-4.8,2.4) D2(-4,2.4) D3(-3.2,2.4) D4(-2.4,2.4) D5(-1.6,2.4) D6(-0.8,2.4) D7(0,2.4) D8(0.8,2.4) D9(1.6,2.4) D10(2.4,2.4) D11(3.2,2.4) D12(4,2.4) D13(4.8,2.4) E1(-4.8,1.6) E2(-4,1.6) E3(-3.2,1.6) E4(-2.4,1.6) E5(-1.6,1.6) E6(-0.8,1.6) E7(0,1.6) E8(0.8,1.6) E9(1.6,1.6) E10(2.4,1.6) E11(3.2,1.6) E12(4,1.6) E13(4.8,1.6) F1(-4.8,0.8) F2(-4,0.8) F3(-3.2,0.8) F4(-2.4,0.8) F5(-1.6,0.8) F6(-0.8,0.8) F7(0,0.8) F8(0.8,0.8) F9(1.6,0.8) F10(2.4,0.8) F11(3.2,0.8) F12(4,0.8) F13(4.8,0.8) G1(-4.8,0) G2(-4,0) G3(-3.2,0) G4(-2.4,0) G5(-1.6,0) G6(-0.8,0) G7(0,0) G8(0.8,0) G9(1.6,0) G10(2.4,0) G11(3.2,0) G12(4,0) G13(4.8,0) H1(-4.8,-0.8) H2(-4,-0.8) H3(-3.2,-0.8) H4(-2.4,-0.8) H5(-1.6,-0.8) H6(-0.8,-0.8) H7(0,-0.8) H8(0.8,-0.8) H9(1.6,-0.8) H10(2.4,-0.8) H11(3.2,-0.8) H12(4,-0.8) H13(4.8,-0.8) J1(-4.8,-1.6) J2(-4,-1.6) J3(-3.2,-1.6) J4(-2.4,-1.6) J5(-1.6,-1.6) J6(-0.8,-1.6) J7(0,-1.6) J8(0.8,-1.6) J9(1.6,-1.6) J10(2.4,-1.6) J11(3.2,-1.6) J12(4,-1.6) J13(4.8,-1.6) K1(-4.8,-2.4) K2(-4,-2.4) K3(-3.2,-2.4) K4(-2.4,-2.4) K5(-1.6,-2.4) K6(-0.8,-2.4) K7(0,-2.4) K8(0.8,-2.4) K9(1.6,-2.4) K10(2.4,-2.4) K11(3.2,-2.4) K12(4,-2.4) K13(4.8,-2.4) L1(-4.8,-3.2) L2(-4,-3.2) L3(-3.2,-3.2) L4(-2.4,-3.2) L5(-1.6,-3.2) L6(-0.8,-3.2) L7(0,-3.2) L8(0.8,-3.2) L9(1.6,-3.2) L10(2.4,-3.2) L11(3.2,-3.2) L12(4,-3.2) L13(4.8,-3.2) M1(-4.8,-4) M2(-4,-4) M3(-3.2,-4) M4(-2.4,-4) M5(-1.6,-4) M6(-0.8,-4) M7(0,-4) M8(0.8,-4) M9(1.6,-4) M10(2.4,-4) M11(3.2,-4) M12(4,-4) M13(4.8,-4) N1(-4.8,-4.8) N2(-4,-4.8) N3(-3.2,-4.8) N4(-2.4,-4.8) N5(-1.6,-4.8) N6(-0.8,-4.8) N7(0,-4.8) N8(0.8,-4.8) N9(1.6,-4.8) N10(2.4,-4.8) N11(3.2,-4.8) N12(4,-4.8) N13(4.8,-4.8)
CC0402
  rect 0.559x0.539 smd: 1(0,0.454) 2(0,-0.454)
CC0603
  rect 0.813x0.813 smd: 1(0,0.762) 2(0,-0.762)
CC0805
  rect 1.27x1.016 smd: 1(0,1.016) 2(0,-1.016)
CC1206
  rect 1.524x1.524 smd: 1(0,1.397) 2(0,-1.397)
CHOKE_3D7_2SP_4W4D5L2H
  rect 1.524x2.54 smd: 1(-1.85,0) 2(1.85,0)
CONN_2D3_4DP_18D2W12D3L_PIP
  round 1.397 hole 1.016: G1(-8.25,10) G2(-8.25,8.2) G3(8.25,10) G4(8.25,8.2)
  round 2.032 hole 1.702: P1(5.05,0) P2(2.75,0) P3(-2.75,0) P4(-5.05,0)
CONNM_1D27X4D05_2X10SP_27D2W
  rect 0.762x2.54 smd: 1(-5.715,-2.025) 2(-5.715,2.025) 3(-4.445,-2.025) 4(-4.445,2.025) 5(-3.175,-2.025) 6(-3.175,2.025) 7(-1.905,-2.025) 8(-1.905,2.025) 9(-0.635,-2.025) 10(-0.635,2.025) 11(0.635,-2.025) 12(0.635,2.025) 13(1.905,-2.025) 14(1.905,2.025) 15(3.175,-2.025) 16(3.175,2.025) 17(4.445,-2.025) 18(4.445,2.025) 19(5.715,-2.025) 20(5.715,2.025)
CONNM_1D27X4D05_2X17SP_36D09W
  rect 0.762x2.54 smd: 1(-10.16,-2.025) 2(-10.16,2.025) 3(-8.89,-2.025) 4(-8.89,2.025) 5(-7.62,-2.025) 6(-7.62,2.025) 7(-6.35,-2.025) 8(-6.35,2.025) 9(-5.08,-2.025) 10(-5.08,2.025) 11(-3.81,-2.025) 12(-3.81,2.025) 13(-2.54,-2.025) 14(-2.54,2.025) 15(-1.27,-2.025) 16(-1.27,2.025) 17(0,-2.025) 18(0,2.025) 19(1.27,-2.025) 20(1.27,2.025) 21(2.54,-2.025) 22(2.54,2.025) 23(3.81,-2.025) 24(3.81,2.025) 25(5.08,-2.025) 26(5.08,2.025) 27(6.35,-2.025) 28(6.35,2.025) 29(7.62,-2.025) 30(7.62,2.025) 31(8.89,-2.025) 32(8.89,2.025) 33(10.16,-2.025) 34(10.16,2.025)
CONNM_2D54X4D65_2X5SP_12D7W5L
  rect 1.016x3.556 smd: 1(5.08,2.325) 2(5.08,-2.325) 3(2.54,2.325) 4(2.54,-2.325) 5(0,2.325) 6(0,-2.325) 7(-2.54,2.325) 8(-2.54,-2.325) 9(-5.08,2.325) 10(-5.08,-2.325)
DFN_D5X3D_10SP_3WL1H_G1
  rect 0.254x0.813 smd: 1(-1,-1.5) 2(-0.5,-1.5) 3(0,-1.5) 4(0.5,-1.5) 5(1,-1.5) 6(1,1.5) 7(0.5,1.5) 8(0,1.5) 9(-0.5,1.5) 10(-1,1.5)
  rect 2.54x1.651 smd: G1(0,0)
DIOZENER_2SP_2D6WX4D5L_AC
  rect 1.778x2.54 smd: A(0,-2.1) C(0,2.1)
DO214AC_3D73_2SP_2D7W4D3L2D44H
  rect 2.083x2.057 smd: A(-1.865,0) C(1.865,0)
GOLD_FINGER_2D54_8X2SP
  rect 1.524x7.518 smd: 1(0,0) 2(-2.54,0) 3(-5.08,0) 4(-7.62,0) 9(0,0) 10(-2.54,0) 11(-5.08,0) 12(-7.62,0) 13(-10.16,0) 14(-12.7,0) 15(-15.24,0) 16(-17.78,0)
  rect 1.524x8.56 smd: 5(-10.16,0.533) 8(-17.78,0.533)
  rect 1.524x8.052 smd: 6(-12.7,0.267) 7(-15.24,0.267)
LC0603
  rect 0.813x0.813 smd: 1(0,0.762) 2(0,-0.762)
LC0805
  rect 1.524x1.27 smd: 1(0,1.016) 2(0,-1.016)
LED_1D4X3D5_4SP_2D7W3D2L1D1H_AC
  rect 1.524x1.016 smd: A1(1.75,-0.7) A2(1.75,0.7) C1(-1.75,-0.7) C2(-1.75,0.7)
MSOP_D5X4D8_10SP_3WL1D09H
  rect 0.254x1.016 smd: 1(-1,-2.4) 2(-0.5,-2.4) 3(0,-2.4) 4(0.5,-2.4) 5(1,-2.4) 6(1,2.4) 7(0.5,2.4) 8(0,2.4) 9(-0.5,2.4) 10(-1,2.4)
MTH_276C138D_8DP_OSP
  round 3.505 hole 3.505 unplated: (0,0)
  round 0.889 hole 0.305: 1(0,2.629) 2(1.859,1.859) 3(2.629,0) 4(1.859,-1.859) 5(0,-2.629) 6(-1.859,-1.859) 7(-2.629,0) 8(-1.859,1.859)
OSC_1D6X2D12_4SP_2D5W3D2L1DH
  rect 1.422x1.219 smd: 1(-1.06,-0.8) 2(1.06,-0.8) 3(1.06,0.8) 4(-1.06,0.8)
RC0402
  rect 0.559x0.539 smd: 1(0,0.454) 2(0,-0.454)
RC0603
  rect 0.813x0.813 smd: 1(0,0.762) 2(0,-0.762)
RC0805
  rect 1.27x1.016 smd: 1(0,1.016) 2(0,-1.016)
RC2512
  rect 3.556x1.778 smd: 1(0,3.175) 2(0,-3.175)
RC_6D15_2SP_9D14W9D4L
  rect 4.318x1.651 smd: 1(-3.075,4.115) 2(3.075,4.115)
  rect 4.318x7.62 smd: 3(-3.075,-1.145) 4(3.075,-1.145)
SO8_3D75X1D27_5SP
  rect 1.219x0.66 smd: 1(2.825,-1.905) 2(2.825,-0.635) 3(2.825,0.635) 4(2.825,1.905)
  custom 1.175x1.175 smd: 5(-0.925,0)
SOD123_3D28_2SP_AC
  rect 1.27x0.889 smd: A(0,-1.64) C(0,1.64)
SOP_1D27X5D165_8SP_3D9W_G95X130
  rect 1.651x0.508 smd: 1(-2.582,1.905) 2(-2.582,0.635) 3(-2.582,-0.635) 4(-2.582,-1.905) 5(2.582,-1.905) 6(2.582,-0.635) 7(2.582,0.635) 8(2.582,1.905)
  rect 2.413x3.302 smd: G1(0,0)
SOT23_1D9X2D_3SP_1D3W3L_GSD
  rect 0.813x1.016 smd: D(0,1) G(-0.95,-1) S(0.95,-1)
SOT23_D95X2D35_5SP_1D6W2D9L
  rect 0.635x1.27 smd: 1(-0.95,-1.175) 2(0,-1.175) 3(0.95,-1.175) 4(0.95,1.175) 5(-0.95,1.175)
TSSOP_D65X5D8_16SP_5L
  rect 1.524x0.381 smd: 1(-2.925,2.339) 8(-2.925,-2.339) 9(2.925,-2.339) 16(2.925,2.339)
  rect 1.524x0.254 smd: 2(-2.925,1.625) 3(-2.925,0.975) 4(-2.925,0.325) 5(-2.925,-0.325) 6(-2.925,-0.975) 7(-2.925,-1.625) 10(2.925,-1.625) 11(2.925,-0.975) 12(2.925,-0.325) 13(2.925,0.325) 14(2.925,0.975) 15(2.925,1.625)
unnamed#2
  round 1.016 smd: (0,0)

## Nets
GND: C1.2 C2.2 C3.2 C4.2 C5.1 C6.2 C7.2 C8.2 C9.1 C10.1 C11.1 C12.2 C13.1 C14.2 C15.2 C16.2 C17.1 C18.1 C19.2 C20.2 C21.2 C22.2 C23.2 C24.2 C25.1 C26.1 C27.1 C28.2 C29.2 C30.2 C31.1 C32.1 C33.2 C34.2 C35.2 C36.2 C37.1 C38.1 C39.2 C40.2 C41.2 C42.2 C43.2 C44.2 C45.1 C46.1 C47.2 C48.2 C49.2 C50.1 C51.1 C52.1 C53.2 C54.1 C55.2 C56.2 C57.2 C58.1 C59.1 C60.2 C61.2 C62.2 C63.2 C64.2 C65.2 C66.2 C67.2 C68.2 C69.2 C71.2 C72.2 C73.2 C74.2 C75.2 C77.2 C78.1 C80.2 C81.2 C82.1 C83.1 C84.2 C85.2 C86.2 C87.1 C88.1 C89.2 C90.2 C91.2 C92.2 C93.1 C94.1 C95.2 C96.2 C97.2 C98.1 C99.2 C100.2 C101.1 C102.1 C103.1 C104.2 C105.2 C106.2 C107.2 C108.1 C109.1 C110.1 C111.2 C112.2 C113.2 C114.2 C115.2 C116.2 C117.1 C118.2 C119.1 C120.2 C121.2 C123.1 C124.1 C125.2 C126.2 C127.1 C128.2 C129.2 C130.2 C131.1 C132.1 C133.2 C134.2 C135.2 C136.2 C138.2 C139.2 C140.2 C141.2 C142.2 C143.2 C144.2 C145.2 C146.2 C147.2 C148.2 C149.2 C150.2 C151.2 C152.2 C153.2 C154.2 C155.2 C156.2 C157.2 C158.2 C159.2 C160.2 C161.2 C162.2 C163.2 C164.2 CONN1.2 CONN1.3 CONN1.6 CONN1.8 CONN1.9 CONN1.11 CONN1.14 CONN1.16 CONN1.17 CONN1.19 CONN1.22 CONN1.23 CONN1.26 CONN1.27 CONN1.30 CONN1.31 CONN1.32 CONN1.33 CONN1.34 CONN2.2 CONN2.3 CONN2.6 CONN2.7 CONN2.10 CONN2.11 CONN2.14 CONN2.15 CONN2.19 CONN2.20 CONN3.2 CONN3.10 CONN4.P3(POWER_1N) CONN4.P4(POWER_2N) D1.A D2.A D3.A OSC1.2(GND) Q1.3(GND) Q2.3(GND) Q4.3(GND) Q6.3(GND) Q8.3(GND) Q10.3(GND) Q12.3(GND) Q14.3(GND) R8.1 R13.1 R18.1 R27.1 R30.1 R35.1 R48.2 R49.2 R50.2 R51.2 R52.2 R53.2 R60.1 R71.2 R72.1 R77.2 R78.2 R79.2 R91.2 R93.2 R96.2 R101.1 R105.1 R110.1 R114.1 R118.1 R123.1 R128.1 R133.1 R137.1 R141.1 R146.1 R149.2 R155.1 R160.1 R167.1 R171.2 U1.G1 U2.5 U2.8 U3.G1 U4.G1 U5.5 U5.8 U6.G1 U7.A1(GND__A1) U7.A13(GND__A13) U7.B8(GND__B8) U7.C3(GND__C3) U7.D2(GND__D2) U7.D5(GND__D5) U7.E2(GND__E2) U7.E11(GND__E11) U7.F3(GND__F3) U7.G7(GND__G7) U7.H12(GND__H12) U7.J4(GND__J4) U7.L9(GND__L9) U7.M6(GND__M6) U7.N1(GND__N1) U7.N13(GND__N13) U8.8(VSS) U9.G1 U10.5 U10.8 U11.G1 U12.4(GND) U12.G1 U13.G1 U14.5 U14.8 U15.G1 U16.G1 U17.5 U17.8 U18.G1 U19.G1 U21.5 U21.8 U22.G1
GND_1: C3.1 C4.1 H1.1 H1.2 H1.3 H1.4 H1.5 H1.6 H1.7 H1.8
GND_2: C22.1 C23.1 H2.1 H2.2 H2.3 H2.4 H2.5 H2.6 H2.7 H2.8
GND_3: C61.1 C63.1 H4.1 H4.2 H4.3 H4.4 H4.5 H4.6 H4.7 H4.8
GND_5: C62.1 C66.1 H5.1 H5.2 H5.3 H5.4 H5.5 H5.6 H5.7 H5.8
GND_6: C21.1 C24.1 H3.1 H3.2 H3.3 H3.4 H3.5 H3.6 H3.7 H3.8
GND_7: C112.1 C114.1 H7.1 H7.2 H7.3 H7.4 H7.5 H7.6 H7.7 H7.8
GND_8: C113.1 C115.1 H6.1 H6.2 H6.3 H6.4 H6.5 H6.6 H6.7 H6.8
GND_9: C138.1 C141.1 H8.1 H8.2 H8.3 H8.4 H8.5 H8.6 H8.7 H8.8
VCC_12P_FAN1_IN: C6.1 C7.1 C8.1 C9.2 L2.2 U1.8(OUT8) U1.9(OUT9) U1.10(OUT0) U2.7
VCC_12P_FAN1_OUT: C12.1 C14.1 C15.1 C16.1 L4.2 U2.6 U3.8(OUT8) U3.9(OUT9) U3.10(OUT0)
VCC_12P_FAN2_IN: C28.1 C29.1 C30.1 C31.2 L6.2 U4.8(OUT8) U4.9(OUT9) U4.10(OUT0) U5.7
VCC_12P_FAN2_OUT: C33.1 C34.1 C35.1 C36.1 L8.2 U5.6 U6.8(OUT8) U6.9(OUT9) U6.10(OUT0)
VCC_12P_FAN3_IN: C47.1 C48.1 C49.1 C50.2 L12.2 U9.8(OUT8) U9.9(OUT9) U9.10(OUT0) U10.7
VCC_12P_FAN3_OUT: C53.1 C55.1 C56.1 C57.1 L14.2 U10.6 U11.8(OUT8) U11.9(OUT9) U11.10(OUT0)
VCC_12P_FAN4_IN: C84.1 C85.1 C86.1 C87.2 L17.2 U13.8(OUT8) U13.9(OUT9) U13.10(OUT0) U14.7
VCC_12P_FAN4_OUT: C89.1 C90.1 C91.1 C92.1 L19.2 U14.6 U15.8(OUT8) U15.9(OUT9) U15.10(OUT0)
VCC_12P_FAN5_IN: C97.1 C98.2 C99.1 C100.1 L21.2 U16.8(OUT8) U16.9(OUT9) U16.10(OUT0) U17.7
VCC_12P_FAN5_OUT: C104.1 C105.1 C106.1 C107.1 L23.2 U17.6 U18.8(OUT8) U18.9(OUT9) U18.10(OUT0)
VCC_12P_FAN6_IN: C118.1 C119.2 C120.1 C121.1 L25.2 U19.8(OUT8) U19.9(OUT9) U19.10(OUT0) U21.7
VCC_12P_FAN6_OUT: C126.1 C128.1 C129.1 C130.1 L27.2 U21.6 U22.8(OUT8) U22.9(OUT9) U22.10(OUT0)
VCC_CL_FAN1F: L3.2 U3.1(IN1) U3.2(IN2) U3.3(IN3)
VCC_CL_FAN1R: L1.2 U1.1(IN1) U1.2(IN2) U1.3(IN3)
VCC_CL_FAN2F: L7.2 U6.1(IN1) U6.2(IN2) U6.3(IN3)
VCC_CL_FAN2R: L5.2 U4.1(IN1) U4.2(IN2) U4.3(IN3)
VCC_CL_FAN3F: L13.2 U11.1(IN1) U11.2(IN2) U11.3(IN3)
VCC_CL_FAN3R: L11.2 U9.1(IN1) U9.2(IN2) U9.3(IN3)
VCC_CL_FAN4F: L18.2 U15.1(IN1) U15.2(IN2) U15.3(IN3)
VCC_CL_FAN4R: L16.2 U13.1(IN1) U13.2(IN2) U13.3(IN3)
VCC_CL_FAN5F: L22.2 U18.1(IN1) U18.2(IN2) U18.3(IN3)
VCC_CL_FAN5R: L20.2 U16.1(IN1) U16.2(IN2) U16.3(IN3)
VCC_CL_FAN6F: L26.2 U22.1(IN1) U22.2(IN2) U22.3(IN3)
VCC_CL_FAN6R: L24.2 U19.1(IN1) U19.2(IN2) U19.3(IN3)
VCCA_FAN_CPLD: C147.1 C151.1 C159.1 C161.1 L9.2 U7.D3(VCCA3__D3) U7.D4(VCCA3__D4) U7.D10(VCCA2__D10) U7.K4(VCCA1__K4) U7.K9(VCCA4__K9)
VDD3P3: C1.1 C2.1 C19.1 C20.1 C39.1 C41.1 C42.1 C43.1 C44.1 C45.2 C60.1 C69.1 C71.1 C72.1 C73.1 C74.1 C75.1 C77.1 C95.1 C96.1 C111.1 C116.1 C133.1 C142.1 C143.1 C144.1 C145.1 C146.1 C148.1 C149.1 C150.1 C152.1 C153.1 C154.1 C155.1 C156.1 C157.1 C158.1 C160.1 C162.1 C163.1 C164.1 CONN3.4 L9.1 L10.2 L15.2 LED1.A1 LED1.A2 LED2.A1 LED2.A2 LED3.A1 LED3.A2 LED4.A1 LED4.A2 LED5.A1 LED5.A2 LED6.A1 LED6.A2 Q1.5(VCC) Q2.5(VCC) Q4.5(VCC) Q6.5(VCC) Q8.5(VCC) Q10.5(VCC) Q12.5(VCC) Q14.5(VCC) R1.2 R2.2 R3.2 R4.2 R5.2 R6.2 R7.1 R9.1 R15.1 R16.2 R19.2 R23.2 R31.1 R32.1 R37.1 R40.1 R41.1 R42.1 R43.1 R54.2 R55.2 R56.2 R57.2 R58.2 R59.2 R61.2 R62.2 R66.1 R73.2 R74.2 R75.2 R76.2 R80.2 R82.2 R83.2 R84.2 R85.2 R86.2 R87.2 R88.2 R90.2 R92.2 R94.2 R95.2 R102.2 R103.1 R104.2 R106.1 R112.1 R121.2 R124.1 R125.1 R129.1 R136.1 R138.1 R142.1 R150.1 R156.1 R157.2 R161.1 R170.1 U7.C6(VCCIO8__C6) U7.C7(VCCIO8__C7) U7.C8(VCCIO8__C8) U7.F2(VCCIO1A__F2) U7.F7(VCC_ONE__F7) U7.F11(VCCIO6__F11) U7.G3(VCCIO1B__G3) U7.G6(VCC_ONE__G6) U7.G8(VCC_ONE__G8) U7.G11(VCCIO6__G11) U7.H7(VCC_ONE__H7) U7.H11(VCCIO5__H11) U7.J3(VCCIO2__J3) U7.J11(VCCIO5__J11) U7.K3(VCCIO2__K3) U7.L6(VCCIO3__L6) U7.L7(VCCIO3__L7) U7.L8(VCCIO3__L8) U8.16(VDD)
VDD3P3_BODE: C79.1 R121.1 R122.2
VDD3P3_EN: C80.1 R119.1 U12.7(EN)
25MHZ_OUT: OSC1.3(OUT) R63.2
25MHZ_OUT_R: R63.1 U7.H6(IO_2_H6/CLK0P/DIFFIO_RX_L18P)
BOARD_ID_0: R170.2 R171.1 U7.M11(IO_3_M11/DIFFIO_TX_RX_B12N)
BOARD_ID_1: R42.2 R50.1 U7.N7(IO_3_N7/DIFFIO_RX_B6N)
BS_VDD3P3: C70.1 U12.1(BS)
CPLD_CONFIG_DONE: R82.1 U7.C5(IO_8_C5/CONF_DONE/DIFFIO_RX_T24)
CPLD_CONFIG_SEL: R78.1 R84.1 U7.D7(IO_8_D7/BOOT_SEL)
CPLD_CRC: R77.1 R83.1 U7.D6(IO_8_D6/CRC_ERROR/DIFFIO_RX_T22)
CPLD_DEV_CLRN: R71.1 R87.1 U7.B9(IO_8_B9/DEV_CLRN/DIFFIO_RX_T16N)
CPLD_DEV_OE: R79.1 R85.1 U7.D8(IO_8_D8/DEV_OE/DIFFIO_RX_T18P)
CPLD_NCONFIG: R86.1 U7.E7(INPUT_ONLY_8_E7/NCONFIG)
CPLD_NSTATUS: R76.1 U7.C4(IO_8_C4/NSTATUS/DIFFIO_RX_T24P)
CPLD_TCK: CONN3.1 R65.2 R99.2 R101.2 U7.G2(IO_1B_G2/TCK/DIFFIO_RX_L11P)
CPLD_TCK_A: R65.1 U7.H1(IO_1B_H1/VREFB1N0)
CPLD_TDI: CONN3.9 R67.2 R97.2 R104.1 U7.F5(IO_1B_F5/TDI/DIFFIO_RX_L12N)
CPLD_TDI_A: R67.1 U7.E1(IO_1A_E1/DIFFIO_RX_L7P)
CPLD_TDO: CONN3.3 R70.2 R100.2 U7.F6(IO_1B_F6/TDO/DIFFIO_RX_L12P)
CPLD_TDO_A: R70.1 U7.D1(IO_1A_D1/DIFFIO_RX_L1N)
CPLD_TMS: CONN3.5 R64.2 R98.2 R102.1 U7.G1(IO_1B_G1/TMS/DIFFIO_RX_L11N)
CPLD_TMS_A: R64.1 U7.H2(IO_1B_H2/DIFFIO_RX_L16N)
CPU_FAN_CPLD_RST_N: CONN2.17 R27.2 U7.D13(IO_6_D13/VREFB6N0)
CPU_UPGRADE_CPLD_TCK: R99.1 U8.6(P02)
CPU_UPGRADE_CPLD_TDI: R97.1 U8.4(P00)
CPU_UPGRADE_CPLD_TDO: R100.1 U8.7(P03)
CPU_UPGRADE_CPLD_TMS: R98.1 U8.5(P01)
CPU_UPGRADE_I2C_INT_L: R92.1 U7.A7(IO_8_A7/DIFFIO_RX_T19P) U8.13(I\N\T\)
EN_FAN1: R9.2 R15.2 U1.7(EN) U3.7(EN) U7.N6(IO_3_N6/DIFFIO_TX_RX_B5N)
EN_FAN2: R31.2 R37.2 U4.7(EN) U6.7(EN) U7.L2(IO_2_L2)
EN_FAN3: R106.2 R112.2 U7.A4(IO_8_A4/DIFFIO_RX_T21P) U9.7(EN) U11.7(EN)
EN_FAN4: R124.2 R129.2 U7.B12(IO_6_B12/DIFFIO_RX_R28P) U13.7(EN) U15.7(EN)
EN_FAN5: R138.2 R142.2 U7.E13(IO_6_E13/CLK3N/DIFFIO_RX_R16N) U16.7(EN) U18.7(EN)
EN_FAN6: R156.2 R161.2 U7.B10(IO_8_B10/DIFFIO_RX_T16P) U19.7(EN) U22.7(EN)
EN_FAN7: CONN1.25 U7.E12(IO_6_E12/DIFFIO_RX_R18N)
EN_FAN8: CONN1.28 U7.F13(IO_6_F13/CLK3P/DIFFIO_RX_R16P)
FAN1_IN_PWM: R10.1 U2.4
FAN1_LED_G: R29.1 U7.M2(IO_2_M2/DIFFIO_RX_L21P)
FAN1_LED_G1: LED1.C1 R29.2
FAN1_LED_R: R28.1 U7.N2(IO_2_N2/DPCLK0/DIFFIO_RX_L22N)
FAN1_LED_R1: LED1.C2 R28.2
FAN1_OUT_PWM: R11.1 U2.3
FAN1_PRESENT: R7.2 U2.16 U7.M7(IO_3_M7/DIFFIO_TX_RX_B5P)
FAN1_PWM: Q4.2(A) U7.N5(IO_3_N5/DIFFIO_RX_B4P)
FAN1_PWM_P: Q3.D R10.2 R11.2 R12.1
FAN1_S_GND: Q3.S R18.2
FAN1_SENSOR_IN: R14.1 R55.1 U7.M4(IO_3_M4/DIFFIO_RX_B2N)
FAN1_SENSOR_IN_R: R14.2 U2.2
FAN1_SENSOR_OUT: R17.2 R54.1 U7.N4(IO_3_N4/DIFFIO_RX_B4N)
FAN1_SENSOR_OUT_R: R17.1 U2.1
FAN1F_VCP: C17.2 U3.4(VCP)
FAN1R_VCP: C10.2 U1.4(VCP)
FAN2_IN_PWM: R33.1 U5.4
FAN2_LED_G: R69.1 U7.J1(IO_2_J1/DIFFIO_RX_L19N)
FAN2_LED_G1: LED2.C1 R69.2
FAN2_LED_R: R68.1 U7.J2(IO_2_J2/DIFFIO_RX_L19P)
FAN2_LED_R1: LED2.C2 R68.2
FAN2_OUT_PWM: R34.1 U5.3
FAN2_PRESENT: R32.2 U5.16 U7.M1(IO_2_M1/DIFFIO_RX_L21N)
FAN2_PWM: Q6.2(A) U7.L1(IO_2_L1/VREFB2N0)
FAN2_PWM_P: Q5.D R33.2 R34.2 R36.1
FAN2_S_GND: Q5.S R60.2
FAN2_SENSOR_IN: R38.1 R61.1 U7.K2(IO_2_K2/DIFFIO_RX_L28P)
FAN2_SENSOR_IN_R: R38.2 U5.2
FAN2_SENSOR_OUT: R39.2 R62.1 U7.K1(IO_2_K1/DIFFIO_RX_L28N)
FAN2_SENSOR_OUT_R: R39.1 U5.1
FAN2F_VCP: C37.2 U6.4(VCP)
FAN2R_VCP: C26.2 U4.4(VCP)
FAN3_IN_PWM: R107.1 U10.4
FAN3_LED_G: R116.1 U7.C11(IO_6_C11/DIFFIO_RX_R29N)
FAN3_LED_G1: LED3.C1 R116.2
FAN3_LED_R: R115.1 U7.A11(IO_8_A11/DIFFIO_RX_T17N)
FAN3_LED_R1: LED3.C2 R115.2
FAN3_OUT_PWM: R108.1 U10.3
FAN3_PRESENT: R103.2 U7.B2(IO_8_B2/DIFFIO_RX_T26N) U10.16
FAN3_PWM: Q8.2(A) U7.A2(IO_8_A2/DIFFIO_RX_T26P)
FAN3_PWM_P: Q7.D R107.2 R108.2 R109.1
FAN3_S_GND: Q7.S R114.2
FAN3_SENSOR_IN: R74.1 R111.1 U7.B3(IO_8_B3/DIFFIO_RX_T23P)
FAN3_SENSOR_IN_R: R111.2 U10.2
FAN3_SENSOR_OUT: R75.1 R113.2 U7.A3(IO_8_A3/DIFFIO_RX_T21N)
FAN3_SENSOR_OUT_R: R113.1 U10.1
FAN3F_VCP: C58.2 U11.4(VCP)
FAN3R_VCP: C51.2 U9.4(VCP)
FAN4_IN_PWM: R126.1 U14.4
FAN4_LED_G: R135.1 U7.D12(IO_6_D12/DIFFIO_RX_R33P)
FAN4_LED_G1: LED4.C1 R135.2
FAN4_LED_R: R134.1 U7.C13(IO_6_C13)
FAN4_LED_R1: LED4.C2 R134.2
FAN4_OUT_PWM: R127.1 U14.3
FAN4_PRESENT: R125.2 U7.A12(IO_6_A12/DIFFIO_RX_R30N) U14.16
FAN4_PWM: Q10.2(A) U7.D11(IO_6_D11/DIFFIO_RX_R33N)
FAN4_PWM_P: Q9.D R126.2 R127.2 R130.1
FAN4_S_GND: Q9.S R133.2
FAN4_SENSOR_IN: R88.1 R131.1 U7.B13(IO_6_B13/DIFFIO_RX_R30P)
FAN4_SENSOR_IN_R: R131.2 U14.2
FAN4_SENSOR_OUT: R80.1 R132.2 U7.C12(IO_6_C12/DIFFIO_RX_R29P)
FAN4_SENSOR_OUT_R: R132.1 U14.1
FAN4F_VCP: C93.2 U15.4(VCP)
FAN4R_VCP: C82.2 U13.4(VCP)
FAN5_IN_PWM: R139.1 U17.4
FAN5_LED_G: R148.1 U7.C1(IO_1A_C1/DIFFIO_RX_L5N)
FAN5_LED_G1: LED5.C1 R148.2
FAN5_LED_R: R147.1 U7.A5(IO_8_A5/DIFFIO_RX_T25P)
FAN5_LED_R1: LED5.C2 R147.2
FAN5_OUT_PWM: R140.1 U17.3
FAN5_PRESENT: R136.2 U7.G13(IO_5_G13/DIFFIO_RX_R11P) U17.16
FAN5_PWM: Q12.2(A) U7.N3(IO_2_N3/DPCLK1/DIFFIO_RX_L22P)
FAN5_PWM_P: Q11.D R139.2 R140.2 R143.1
FAN5_S_GND: Q11.S R146.2
FAN5_SENSOR_IN: R144.1 U7.A8(IO_8_A8/DIFFIO_RX_T15P)
FAN5_SENSOR_IN_R: R144.2 U17.2
FAN5_SENSOR_OUT: R145.2 U7.A9(IO_8_A9/DIFFIO_RX_T15N)
FAN5_SENSOR_OUT_R: R145.1 U17.1
FAN5F_VCP: C110.2 U18.4(VCP)
FAN5R_VCP: C103.2 U16.4(VCP)
FAN6_IN_PWM: R158.1 U21.4
FAN6_LED_G: R169.1 U7.C10(IO_8_C10/DIFFIO_RX_T14P)
FAN6_LED_G1: LED6.C1 R169.2
FAN6_LED_R: R168.1 U7.C9(IO_8_C9/DIFFIO_RX_T14N)
FAN6_LED_R1: LED6.C2 R168.2
FAN6_OUT_PWM: R159.1 U21.3
FAN6_PRESENT: R150.2 U7.H13(IO_5_H13/DIFFIO_RX_R9N) U21.16
FAN6_PWM: Q14.2(A) U7.M5(IO_3_M5/DIFFIO_RX_B2P)
FAN6_PWM_P: Q13.D R158.2 R159.2 R162.1
FAN6_S_GND: Q13.S R167.2
FAN6_SENSOR_IN: R163.1 U7.A6(IO_8_A6/DIFFIO_RX_T19N)
FAN6_SENSOR_IN_R: R163.2 U21.2
FAN6_SENSOR_OUT: R165.2 U7.B7(IO_8_B7/VREFB8N0)
FAN6_SENSOR_OUT_R: R165.1 U21.1
FAN6F_VCP: C131.2 U22.4(VCP)
FAN6R_VCP: C123.2 U19.4(VCP)
FAN7_LED_G: CONN1.5 U7.K11(IO_5_K11/DIFFIO_RX_R2P)
FAN7_LED_R: CONN1.7 U7.J13(IO_5_J13/DIFFIO_RX_R9P)
FAN7_PRESENT: CONN1.21 R4.1 U7.G12(IO_5_G12/DIFFIO_RX_R11N)
FAN7_PWM: Q2.2(A) U7.L4(IO_3_L4/DIFFIO_TX_RX_B1P)
FAN7_SENSOR_IN: CONN1.13 R1.1 U7.M13(IO_3_M13/DIFFIO_TX_RX_B10N)
FAN7_SENSOR_OUT: CONN1.15 R2.1 U7.L12(IO_5_L12/DIFFIO_RX_R2N)
FAN8_LED_G: CONN1.10 U7.M8(IO_3_M8/DIFFIO_RX_B8N)
FAN8_LED_R: CONN1.12 U7.N9(IO_3_N9/DIFFIO_RX_B11P)
FAN8_PRESENT: CONN1.24 R3.1 U7.G10(IO_6_G10/CLK2N/DIFFIO_RX_R14N)
FAN8_PWM: Q1.2(A) U7.L5(IO_3_L5/DIFFIO_TX_RX_B1N)
FAN8_SENSOR_IN: CONN1.18 R5.1 U7.M10(IO_3_M10/DIFFIO_TX_RX_B16N)
FAN8_SENSOR_OUT: CONN1.20 R6.1 U7.N11(IO_3_N11/VREFB3N0)
FAN_12V: C5.2 C13.2 C25.2 C32.2 C46.2 C54.2 C65.1 C67.1 C68.1 C78.2 C88.2 C101.2 C108.2 C117.2 C127.2 C134.1 C135.1 C136.1 D3.C L1.1 L2.1 L3.1 L4.1 L5.1 L6.1 L7.1 L8.1 L11.1 L12.1 L13.1 L14.1 L16.1 L17.1 L18.1 L19.1 L20.1 L21.1 L22.1 L23.1 L24.1 L25.1 L26.1 L27.1 R12.2 R36.2 R109.2 R119.2 R130.2 R143.2 R162.2 R166.1 U12.2(IN) U20.9(OUT) U23.1(S1) U23.2(S2) U23.3(S3)
FAN_12V_PDU: C137.1 C139.1 C140.1 CONN4.P1(POWER_1P) CONN4.P2(POWER_2P) R152.2 R164.4 R166.2
FAN_BOT_HS_PGD: C125.1 CONN2.18 R157.1 U20.8(PGD)
FAN_IN_3V3_25M_EN: OSC1.1(\\S\T/OE) R66.2
FAN_IN_3V3_25M_VCC: C40.1 L10.1 OSC1.4(VDD)
FAN_INT_L: CONN2.1 U7.F12(IO_6_F12/DIFFIO_RX_R18P)
FAN_SCL1_R: R45.1 R57.1 U7.K12(IO_5_K12/DIFFIO_RX_R7P)
FAN_SCL2_R: R46.1 R58.1 U7.K13(IO_5_K13/VREFB5N0)
FAN_SDA1_R: R44.1 R56.1 U7.L13(IO_5_L13)
FAN_SDA2_R: R47.1 R59.1 U7.J12(IO_5_J12/DIFFIO_RX_R7N)
FAN_SDA_1_E: R89.2 U8.15(SDA)
FAN_SDA_1_R: R81.1 U7.B11(IO_6_B11/DIFFIO_RX_R28N)
FAN_TOP_HS_PGD: CONN1.29 CONN2.16 R16.1
FB_VDD3P3: C79.2 R120.1 R122.1 U12.5(FB)
GPIO_1: R72.2 R73.1 U7.B1(IO_1A_B1/DIFFIO_RX_L5P)
HS_GATE: U20.10(GATE) U23.4(G)
HS_MOS_D: R164.3 U23.5(D)
HS_OV: R151.2 R154.1 U20.4(OVLO)
HS_PWR: R153.2 U20.7(PWR)
HS_SENSE: R164.1 U20.1(SENSE)
HS_TIMER: C122.1 U20.6(TIMER)
HS_UV: R152.1 R154.2 U20.3(UVLO)
HS_VIN: D2.C R164.2 U20.2(VIN)
I2C_ FAN_MNGMT_SCL: R20.2 U7.A10(IO_8_A10/DIFFIO_RX_T17P) U8.14(SCL)
I2C_ FAN_MNGMT_SDA: R24.2 R81.2 R89.1
I2C_FAN_BOT_SCL: R22.2 R45.2
I2C_FAN_BOT_SDA: R21.2 R44.2
I2C_FAN_TOP_SCL: R25.2 R46.2
I2C_FAN_TOP_SDA: R26.2 R47.2
I2C_SCL_LC1_R: CONN2.8 R22.1
I2C_SCL_LC2_R: CONN2.12 R25.1
I2C_SCL_MNGMT: CONN2.4 R19.1 R20.1
I2C_SDA_LC1_R: CONN2.9 R21.1
I2C_SDA_LC2_R: CONN2.13 R26.1
I2C_SDA_MNGMT: CONN2.5 R23.1 R24.1
ILIM_FAN1F: R13.2 U3.5(ILIM)
ILIM_FAN1R: R8.2 U1.5(ILIM)
ILIM_FAN2F: R35.2 U6.5(ILIM)
ILIM_FAN2R: R30.2 U4.5(ILIM)
ILIM_FAN3F: R110.2 U11.5(ILIM)
ILIM_FAN3R: R105.2 U9.5(ILIM)
ILIM_FAN4F: R128.2 U15.5(ILIM)
ILIM_FAN4R: R123.2 U13.5(ILIM)
ILIM_FAN5F: R141.2 U18.5(ILIM)
ILIM_FAN5R: R137.2 U16.5(ILIM)
ILIM_FAN6F: R160.2 U22.5(ILIM)
ILIM_FAN6R: R155.2 U19.5(ILIM)
LGND_FAN12V: C122.2 C137.2 R149.1 R151.1 R153.1 U20.5(GND)
LGND_VDD3P3: C76.2 R118.2 R120.2
PCA9534PW_A0: R90.1 R91.1 U8.1(A0)
PCA9534PW_A1: R93.1 R94.1 U8.2(A1)
PCA9534PW_A2: R95.1 R96.1 U8.3(A2)
PWM_OUT1: Q3.G Q4.4(Y)
PWM_OUT2: Q5.G Q6.4(Y)
PWM_OUT3: Q7.G Q8.4(Y)
PWM_OUT4: Q9.G Q10.4(Y)
PWM_OUT5: Q11.G Q12.4(Y)
PWM_OUT6: Q13.G Q14.4(Y)
PWM_OUT7: CONN1.1 Q2.4(Y)
PWM_OUT8: CONN1.4 Q1.4(Y)
SS_VDD3P3: C76.1 U12.8(SS)
SST_FAN1F: C18.2 U3.6(SST)
SST_FAN1R: C11.2 U1.6(SST)
SST_FAN2F: C38.2 U6.6(SST)
SST_FAN2R: C27.2 U4.6(SST)
SST_FAN3F: C59.2 U11.6(SST)
SST_FAN3R: C52.2 U9.6(SST)
SST_FAN4F: C94.2 U15.6(SST)
SST_FAN4R: C83.2 U13.6(SST)
SST_FAN5F: C109.2 U18.6(SST)
SST_FAN5R: C102.2 U16.6(SST)
SST_FAN6F: C132.2 U22.6(SST)
SST_FAN6R: C124.2 U19.6(SST)
SW_VDD3P3: C70.2 D1.C L15.1 R117.2 U12.3(SW)
SW_VDD3P3_PLL_C: C64.1 R117.1
TMP1_CLKOUT_N: R52.1 U7.M3(IO_2_M3/PLL_L_CLKOUTN/DIFFIO_RX)
TMP1_CLKOUT_P: R53.1 U7.L3(IO_2_L3/PLL_L_CLKOUTP/DIFFIO_RX)
VERSION_ID_0: R41.2 R49.1 U7.M12(IO_3_M12/DIFFIO_TX_RX_B10P)
VERSION_ID_1: R40.2 R48.1 U7.N12(IO_3_N12)
VERSION_ID_2: R43.2 R51.1 U7.N8(IO_3_N8/DIFFIO_RX_B6P)
VREG5_VDD3P3: C81.1 U12.6(VREG5)

Pads without a net: CONN3 6 7 8; CONN4 G1 G2 G3 G4; Q1 1; Q2 1; Q4 1; Q6 1; Q8 1; Q10 1; Q12 1; Q14 1; U2 9 10 11 12 13 14 15; U5 9 10 11 12 13 14 15; U7 B4 B5 B6 C2 D9 E3 E4 E5 E6 E8 E9 E10 F1 F4 F8 F9 F10 G4 G5 G9 H3 H4 H5 H8 H9 H10 J5 J6 J7 J8 J9 J10 K5 K6 K7 K8 K10 L10 L11 M9 N10; U8 9 10 11 12; U10 9 10 11 12 13 14 15; U14 9 10 11 12 13 14 15; U17 9 10 11 12 13 14 15; U21 9 10 11 12 13 14 15

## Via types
v1: diameter 0.762, hole 0.381, TOP to BOTTOM, 277 vias
v2: diameter 0.508, hole 0.254, TOP to BOTTOM, 97 vias
v3: diameter 0.559, hole 0.305, TOP to BOTTOM, 1560 vias

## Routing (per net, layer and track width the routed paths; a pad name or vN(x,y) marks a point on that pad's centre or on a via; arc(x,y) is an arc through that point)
GND: length 323.5
  TOP w0.254: U7.N13 v2(125.48,13.34) ; U7.F3 v2(131.88,22.14) U7.E2 v2(132.68,22.94) 132.68,22.94 U7.D2 ; U7.A1 135.74,23.6 v2(136.03,23.6) ; U7.C3 v2(134.28,22.14) ; U7.G7 v2(131.08,18.94) ; v2(135.08,17.35) 135.07,17.35 U7.B8 ; U7.M6 v2(127.08,18.94) ; U7.A13 v2(135.88,13.34) ; U7.N1 v2(125.48,23.74) ; U7.J4 v2(129.48,21.34) ; U7.D5 v2(132.68,20.54) ; U7.H12 v2(129.48,14.14) ; U7.L9 v2(127.88,16.54)
  TOP w0.381: C131.1 387.53,29.69 v3(387.53,29.97) ; v3(13.46,34.8) 14.32,34.8 Q1.3 ; v3(85.54,2.79) C24.2 v3(86.36,3.68) ; CONN3.10 v3(172.86,21.83) ; C97.2 301.93,32.44 301.62,32.13 ; C97.2 301.93,33.98 C100.2 ; C97.2 v3(300.99,32.77) ; 377.06,30.99 R155.1 377.77,30.17 v3(377.95,30.35) ; CONN1.19 v3(5.25,24.09) ; U8.8 157.93,15.68 157.48,16.13 v3(157.48,17.1) ; v3(20.25,33.96) C3.2 v3(19.43,34.8) ; v3(317.63,26.8) 317.45,26.62 C110.1 ; R91.2 R93.2 v3(151.99,9.64) ; v3(9.37,28.07) 9.54,27.9 CONN1.14 ; v3(25.15,23.24) 24.97,23.06 C4.2 ; 317.37,27.81 317.32,27.76 R141.1 316.18,28.07 v3(315.47,28.07) ; v3(391.03,31.5) 390.45,31.5 C133.2 ; CONN2.7 v3(59.14,7.95) ; CONN2.3 56.6,8.44 v3(56.13,7.98) ; C110.1 317.45,24.69 317.5,24.64 ; C110.1 318.52,25.78 ; C9.1 30.53,40.01 v3(30.02,39.5) ; CONN2.2 v3(55.33,15.75) ; R72.1 144.17,25.91 v3(144.4,25.68) ; CONN2.6 v3(57.87,15.72) ; C119.1 v3(369.7,38.99) ; v3(376.17,31.75) 376.23,31.8 C124.1 377.88,31.8 ; R52.2 v3(118.12,25.53) ; v3(196.78,37.39) C61.2 v3(195.96,38.23) ; v3(379.2,23.21) 380.05,24.06 C127.1 ; R79.2 v3(141.74,17.27) ; C69.2 v3(215.39,47.88) ; v2(132.68,15.73) 132.67,15.73 132.28,15.34 U7.E11 ; 307.59,28.57 307.9,28.27 R137.1 309.06,28.27 309.25,28.45 ; CONN1.2 v3(9.23,35.52) ; C16.2 38.15,36.01 C14.2 v3(37.34,34.54) ; CONN1.9 v3(8.98,30.44) ; v3(163.86,19.58) 162.88,19.58 CONN3.2 ; v3(376.78,20.19) 377.63,20.19 D2.A 377.64,21.34 376.98,21.34 v3(376.77,21.55) ; CONN1.22 9.94,22.82 v3(9.4,22.27) ; v3(78.23,47.75) C23.2 v3(77.34,46.94) ; Q10.3 v3(254.83,35.37) ; C117.1 369.52,30.41 v3(369.19,30.73) ; 385.83,32.77 386.13,33.07 C132.1 387.55,33.07 v3(387.73,32.89) ; CONN2.14 62.95,12.49 v3(63.5,11.94) ; CONN1.8 v3(9.31,31.71) ; R71.2 142.56,15.1 142.56,14.72 142.76,14.52 143.92,14.52 v3(144.11,14.7) ; v3(315.36,29.23) 315.57,29.23 315.67,29.14 C109.1 317.32,29.14 317.37,29.08 ; C95.2 v3(253.87,32) ; C101.1 v3(306.5,23.82) ; CONN2.19 v3(66.76,7.95) ; C112.2 v3(335.97,5.92) ; C15.2 37.41,38.79 C12.2 ; CONN1.31 v3(8.98,16.47) CONN1.32 ; v3(61.39,11.81) 61.39,11.76 61.68,11.48 CONN2.11 ; CONN1.6 v3(9.23,32.98) ; C130.2 381,36.01 v3(381,35.31) ; CONN1.3 v3(9.1,34.25) ; v3(369.16,34.32) 369.57,33.91 C118.2 ; v3(60.58,11.81) 60.58,12.23 60.41,12.41 CONN2.10 ; v3(69.98,3.68) C21.2 v3(70.79,2.79) ; CONN1.27 v3(5.29,19.01) ; CONN2.15 v3(64.22,7.92) ; v3(378.97,41.27) C126.2 ; R53.2 v3(118.11,24.51) ; CONN1.33 v3(8.98,15.2) ; C116.2 v3(353.26,48.59) ; C125.2 v3(377.82,2.81) ; v3(66.76,15.68) CONN2.20 ; C44.2 151.99,17.68 v3(151.99,16.88) ; C2.2 18.16,35.42 v3(18.79,36.05) ; C1.2 v3(14.22,36.07) ; v3(9.21,27.22) 9.21,27.11 9.69,26.63 CONN1.16 ; CONN1.11 v3(8.98,29.17) ; 307.47,29.46 307.52,29.52 C102.1 309.32,29.52 309.37,29.46 ; CONN1.26 v3(9.36,20.28) ; v3(70.1,40.51) C22.2 v3(70.92,41.4) ; v3(161.73,24.18) 161.93,24.18 C45.1 ; C88.1 v3(241.05,33.66) ; C114.2 v3(352.12,5.77) ; C42.2 v3(146.56,47.88) ; v3(309.19,25.45) C103.1 309.19,27.25 309.25,27.3 ; C53.2 174.88,37.97 ; CONN1.17 v3(5.17,25.36) ; C111.2 v3(323.34,28.32) ; C142.2 v3(420.5,50.16) ; v3(301.12,38.1) 301.93,38.1 C98.1 ; C104.2 v3(310.39,32.26) ; CONN1.23 v3(5.21,21.55) ; R146.1 v3(323.85,36.32) ; v3(141.74,18.63) 141.75,18.63 141.83,18.54 142.42,18.54 R78.2 R77.2 ; R133.1 v3(256.03,37.21) ; v3(204.34,30.61) C63.2 v3(203.45,31.42) ; CONN1.34 v3(11.17,13.97) ; R27.1 v3(64.19,6.86) ; C108.1 v3(314.91,23.44) ; v3(387.6,31.37) 387.42,31.19 R160.1 386.71,32 386.59,32.13 ; C123.1 377.44,28.07 v3(377.82,28.45) ; Q12.3 v3(324.67,31.68) ; R101.1 v3(163.14,11.88) ; Q14.3 v3(394.11,35.2) ; C43.2 v3(150.98,16.87) ; C105.2 v3(310.39,37.47) ; R96.2 v3(155.04,9.63) ; CONN1.30 v3(9.31,17.74)
  TOP w0.508: C72.2 v3(215.8,18.85) ; 105.41,35.18 105.46,35.23 C34.2 ; v3(103.63,32.89) C32.1 104.34,31.57 104.52,31.75 ; 231.01,37.34 231.19,37.16 C84.2 ; C80.2 225.67,23.6 v3(225.69,23.57) ; 370.2,32.89 370.26,32.95 C118.2 ; v3(403.17,21.66) C140.2 C139.2 v3(401.19,22.48) ; C30.2 98.99,37.77 C31.1 98.42,38.99 v3(98.17,38.73) ; C83.1 228.73,31.37 ; C83.1 229.29,30.79 ; C83.1 229.29,32.08 ; C28.2 96.72,37.54 C29.2 ; C28.2 94.05,37.54 93.98,37.47 ; C28.2 v3(95.25,38.35) ; 33.91,30.35 R8.1 34.62,29.66 ; 87.47,38.83 87.32,38.68 C25.1 v3(88.27,38.23) ; C90.2 242.12,38.53 C92.2 ; C90.2 242.12,36.63 ; C90.2 v3(241.17,37.34) ; C38.1 R35.1 112.09,31.57 ; C38.1 112.09,33.45 112.14,33.4 ; C38.1 110.31,33.45 v3(110.24,33.53) ; C141.2 v3(409.14,29.41) ; C60.2 v3(187.83,32) ; C6.2 28.12,33.86 ; C6.2 28.12,35.23 ; C6.2 v3(27.3,34.54) ; v3(167.55,39.19) 167.98,39.62 C50.1 ; Q8.3 v3(188.98,35.37) ; C68.2 213.13,26.9 ; C20.2 v3(69.09,45.47) ; R167.1 v3(396.37,37.85) ; 36.86,26.77 37.01,26.62 C13.1 v3(37.47,27.56) ; v3(172.72,30.61) 172.59,30.48 R105.1 ; C26.1 v3(88.39,31.24) ; C135.2 v3(391.8,3.81) ; 176.15,33.53 176.33,33.71 C55.2 ; 241.81,32.89 241.37,32.46 C88.1 ; v3(372.87,13.72) 372.87,12.95 R149.2 373.89,12.95 v3(373.89,13.72) ; R60.1 v3(121.54,37.08) ; C84.2 v3(232.28,38.23) ; C84.2 233.75,37.16 C85.2 ; C27.1 91.44,31.75 ; C27.1 92.26,31.17 ; C27.1 92.26,32.69 v3(92.33,32.77) ; Q4.3 v3(51.37,36.89) ; C115.2 352.37,39.7 v3(352.55,39.88) ; C47.2 v3(165.99,34.54) ; C47.2 166.8,33.71 ; C47.2 166.8,36.01 C49.2 ; C51.1 v3(173.1,27.69) ; C59.1 182.83,31.55 ; C59.1 182.12,30.99 ; C59.1 181.18,31.55 v3(181.1,31.62) ; C96.2 v3(282.07,45.59) ; C34.2 105.46,37.92 C36.2 ; C34.2 v3(104.65,36.45) ; 90.37,31.04 R30.1 91.06,31.75 ; C82.1 v3(225.43,30.86) ; C57.2 176.33,36.01 C55.2 ; C55.2 v3(175.13,34.54) ; 26.75,26.9 27.03,26.62 C5.1 v3(27.43,27.56) ; 182.83,29.66 R110.1 182.12,30.35 ; 175.01,26.8 175.19,26.62 C54.1 v3(175.64,27.56) ; 165.48,26.8 165.66,26.62 C46.1 v3(166.12,27.56) ; v3(235.84,38.35) 236.47,38.99 C87.1 ; C93.1 v3(249.05,30.48) ; R49.2 R48.2 118.89,14.05 v3(119.89,14.05) ; C33.2 104.19,40.95 ; C67.2 212.12,26.9 ; C18.1 44.52,31.55 44.83,31.24 ; C18.1 43,31.55 v3(42.93,31.62) ; C18.1 R13.1 44.78,29.66 44.83,29.72 ; 248.97,32.46 R128.1 248.28,33.15 ; R114.1 v3(189.99,37.21) ; C41.2 v3(138.43,33.66) ; v3(223.16,28.04) R118.1 v3(225.7,28.04) ; C66.2 v3(211.66,3.86) ; C138.2 v3(402.28,36.27) ; OSC1.2 v3(130,33.7) ; v3(247.27,34.42) 247.34,34.34 C94.1 ; v3(135.2,31.8) 134.6,31.8 C40.2 ; D1.A 208.32,18.34 C64.2 206.63,18.06 207.24,17.45 v3(208.02,17.45) ; 249.05,34.16 248.87,34.34 C94.1 ; Q2.3 v3(18.73,39.43) ; C62.2 v3(196.78,5.92) ; C91.2 242.12,41.22 C89.2 241.05,42.42 ; C58.1 v3(182.63,27.69) ; C73.2 216.81,18.8 v3(216.76,18.85) 216.76,18.85 ; 173.48,31.5 173.43,31.55 C52.1 171.65,31.55 v3(171.58,31.62) ; R18.1 v3(50.67,38.73) ; C71.2 v3(214.78,18.9) ; C39.2 v3(119.13,31.88) ; C10.1 v3(34.42,27.69) ; C134.2 v3(390.65,3.94) ; v3(225.3,37.85) C78.1 224.36,38.3 224.54,38.48 ; C11.1 33.2,31.55 ; C11.1 33.91,30.86 ; C11.1 34.49,31.55 ; C17.1 v3(44.45,27.69) ; R51.2 R50.2 v3(120.14,18.16) ; C113.2 v3(336.48,38.03) ; C19.2 v3(50.04,33.53) ; C37.1 v3(111.76,29.59) ; 228.09,31.37 R123.1 227.4,30.66 ; C94.1 248.28,33.66 ; C12.2 36.7,38.1 ; C81.2 v3(225.7,22.58) ; C136.2 v3(392.94,3.81) ; Q6.3 v3(120.21,35.24)
  BOTTOM w0.381: C157.2 130.56,11.94 130.11,12.38 130.11,12.65 ; C157.2 130.56,10.67 130.3,10.41 ; C157.2 129.67,11.68 ; C152.2 129.82,24.99 v3(129.18,25.63) 128.8,25.25 C149.2 ; C143.2 127.03,19 v2(127.08,18.94) ; C146.2 127.45,16.82 127.73,16.54 v2(127.88,16.54) ; 130.68,12.78 C154.2 130.1,13.26 ; C159.2 133.02,15.39 v2(132.68,15.73) ; v2(129.48,14.14) 129.36,14.02 C148.2 ; C145.2 126.55,22.52 126.93,22.14 v2(127.08,22.14) ; 131.83,25.4 131.85,25.37 C158.2 ; v3(120.8,13.99) 120.83,14.02 R171.2 ; v2(134.28,22.14) 134.69,22.55 C161.2 ; C156.2 130.28,17.83 v2(130.28,17.34) ; C151.2 129.54,18.89 v2(129.48,18.94) 129.09,19.34 C150.2 ; C144.2 125.62,23.88 v2(125.48,23.74) ; C153.2 129.47,21.36 v2(129.48,21.34) ; C148.2 128.2,14.02 ; C148.2 128.78,13.34 ; v3(130.52,25.76) 130.84,25.45 C155.2 ; C160.2 C162.2 135.77,20.65 136.36,20.05 v3(136.85,20.05) ; v2(129.48,20.54) 128.76,20.54 C147.2
  BOTTOM w0.508: v3(141.24,13.73) 141.23,13.73 141.12,13.84 C164.2 ; v3(139.95,15.01) 139.93,15.01 139.57,15.37 C163.2
  vias: v1(36.7,45.85) v1(63.12,35.18) v1(66.98,4.8) v1(69.72,31.37) v1(98.42,35.31) v1(100.46,24.77) v1(105.6,45.85) v1(108.58,26.54) v1(115.19,32.51) v1(130.68,35.56) v1(142.88,31.75) v1(174.5,45.85) v1(243.4,45.85) v1(245.87,26.54) v1(271.02,49.91) v2(30.05,31.11) v2(30.99,31.11) v2(31.93,31.11) v2(40.08,31.11) v2(41.02,31.11) v2(41.96,31.11) v2(91.82,35.61) v2(91.82,34.67) v2(91.82,33.73) v2(107.39,33.02) v2(108.33,33.02) v2(109.27,33.02) v2(168.73,31.11) v2(169.67,31.11) v2(170.61,31.11) v2(178.26,31.11) v2(179.2,31.11) v2(180.14,31.11) v2(218.64,24.75) v2(218.64,23.81) v2(218.64,22.87) v2(218.64,21.93) v2(219.56,24.75) v2(219.56,23.81) v2(219.56,22.87) v2(219.56,21.93) v2(228.85,35.23) v2(228.85,34.29) v2(228.85,33.35) v2(244.42,33.91) v2(245.36,33.91) v2(246.3,33.91) v2(304.62,29.08) v2(305.56,29.08) v2(306.5,29.08) v2(312.62,28.7) v2(313.56,28.7) v2(314.5,28.7) v2(373.2,31.49) v2(374.14,31.49) v2(375.08,31.49) v2(382.85,32.51) v2(383.79,32.51) v2(384.73,32.51) v3(1.31,53.67) v3(1.3,49.02) v3(1.32,37.17) v3(1.32,32.36) v3(1.32,28.42) v3(1.32,21) v3(1.28,15.62) v3(1.31,11.97) v3(1.33,5.5) v3(1.33,1.33) v3(1.35,43.12) v3(1.36,24.48) v3(2.29,7.87) v3(2.41,21.59) v3(2.79,32.38) v3(2.79,26.04) v3(2.92,37.47) v3(3.17,3.05) v3(4.45,8.38) v3(4.7,45.59) v3(4.83,42.67) v3(5.33,1.4) v3(6.47,53.68) v3(7.24,47.62) v3(8.38,4.57) v3(8.51,52.2) v3(9.12,1.4) v3(10.79,5.08) v3(11.43,50.29) v3(11.82,53.7) v3(12.83,44.32) v3(13.74,1.4) v3(14.3,50.61) v3(14.29,45.81) v3(14.31,41.9) v3(15.49,3.94) v3(16.89,41.01) v3(18.12,1.42) v3(18.41,4.83) v3(20.1,40.98) v3(21.26,1.3) v3(21.59,15.88) v3(25.19,41.01) v3(25.4,15.24) v3(25.84,1.34) v3(26.67,4.57) v3(26.92,38.1) v3(26.92,36.07) v3(27.8,41) v3(28.42,43.76) v3(28.42,41.85) v3(28.45,46.1) v3(28.45,45.29) v3(28.76,1.32) v3(29.08,31.5) v3(29.08,30.61) v3(29.27,46.1) v3(29.27,45.29) v3(31.09,4.09) v3(31.5,8.13) v3(32.4,1.3) v3(32.89,31.62) v3(32.89,30.61) v3(33.27,10.16) v3(34.75,3.86) v3(35.05,8.13) v3(35.69,13.84) v3(36.07,10.54) v3(36.2,46.74) v3(36.28,1.28) v3(36.83,37.21) v3(36.83,36.32) v3(36.83,35.43) v3(37.01,46.74) v3(37.82,46.74) v3(37.82,45.92) v3(38.53,3.96) v3(39.12,31.62) v3(39.12,30.73) v3(39.12,8.26) v3(39.44,1.3) v3(39.5,13.84) v3(40.51,10.41) v3(42.37,3.96) v3(42.93,30.61) v3(43.9,1.36) v3(45.09,13.84) v3(45.97,32.13) v3(46.08,4.01) v3(46.86,30.35) v3(47.34,43.95) v3(48.26,1.28) v3(49.13,41) v3(49.15,10.29) v3(49.28,8.13) v3(49.81,3.94) v3(51.44,29.84) v3(51.56,11.81) v3(51.56,7.49) v3(51.69,34.67) v3(51.69,9.91) v3(51.88,1.32) v3(52.78,41.01) v3(53.64,3.94) v3(54.88,1.28) v3(55.5,31.5) v3(56.31,41) v3(57.4,3.3) v3(58.55,34.67) v3(58.55,29.72) v3(58.96,1.28) v3(61.94,53.66) v3(61.9,48.72) v3(61.92,44.16) v3(61.94,41.08) v3(62.61,31.37) v3(62.89,1.3) v3(63.7,50.96) v3(64.9,47.88) v3(64.9,43.81) v3(65.62,53.68) v3(66.8,29.72) v3(66.93,34.8) v3(67.14,1.28) v3(67.31,2.67) v3(67.69,50.8) v3(69.34,4.19) v3(69.48,53.68) v3(71.1,1.28) v3(71.75,50.8) v3(72.01,6.99) v3(72.52,29.72) v3(73.16,53.66) v3(74.68,1.4) v3(74.93,50.8) v3(76.78,53.68) v3(78.49,50.55) v3(79.76,44.58) v3(80.01,47.24) v3(81.16,52.02) v3(82.5,1.28) v3(82.74,53.6) v3(82.74,48.68) v3(82.75,45.56) v3(82.75,42.55) v3(83.97,41.01) v3(86.88,1.28) v3(87.05,41.01) v3(87.76,2.92) v3(89.85,41.01) v3(91.31,32.77) v3(91.44,36.58) v3(92.1,1.28) v3(92.33,36.58) v3(93.6,2.67) v3(93.99,41.01) v3(96.06,1.3) v3(96.39,38.73) v3(97.31,43.57) v3(97.28,41.04) v3(97.28,38.73) v3(97.35,46.1) v3(97.35,45.29) v3(98.17,46.1) v3(98.17,45.29) v3(98.42,2.29) v3(101.14,1.3) v3(102.49,9.73) v3(103.3,9.73) v3(103.89,2.67) v3(104.11,9.73) v3(104.27,40.01) v3(104.27,38.99) v3(104.27,37.97) v3(104.44,1.3) v3(105.1,46.74) v3(105.91,46.74) v3(106.43,33.53) v3(106.43,32.64) v3(106.72,46.74) v3(106.72,45.92) v3(108.48,1.3) v3(110.24,32.51) v3(111.25,2.67) v3(112.06,1.3) v3(115.57,1.3) v3(116.24,44.06) v3(118.72,41.01) v3(119.46,1.3) v3(121.54,2.29) v3(122.64,40.96) v3(122.86,1.3) v3(124.46,39.37) v3(125.22,33.27) v3(126.62,36.83) v3(126.92,25.68) v3(127.08,1.3) v3(127.52,40.98) v3(128.57,9.17) v3(129.41,10.03) v3(129.41,9.17) v3(129.79,37.72) v3(130.44,53.7) v3(130.43,49.4) v3(130.43,45.72) v3(130.43,42.04) v3(130.63,1.3) v3(132.08,42.55) v3(132.84,36.83) v3(133.35,50.29) v3(133.6,44.32) v3(133.73,47.37) v3(133.86,41.66) v3(134.24,1.3) v3(134.78,53.68) v3(136.91,34.54) v3(137.03,50.55) v3(137.16,37.72) v3(138.72,53.64) v3(138.66,1.3) v3(139.19,44.45) v3(140.46,50.67) v3(141.73,35.56) v3(142.49,45.21) v3(142.82,53.64) v3(142.91,1.29) v3(144.4,50.67) v3(145.95,1.3) v3(147.11,53.64) v3(147.83,34.54) v3(148.34,39.24) v3(148.46,50.93) v3(148.84,47.24) v3(148.97,43.69) v3(150.44,1.3) v3(152.05,53.62) v3(152.09,49.42) v3(152.1,45.98) v3(152.09,43.02) v3(153.16,41.01) v3(154.31,37.34) v3(154.31,32.26) v3(154.54,1.3) v3(157.08,41.01) v3(157.76,1.3) v3(159.13,33.27) v3(160.15,38.73) v3(161.54,1.3) v3(162.73,41) v3(164.92,1.3) v3(165.61,38.1) v3(165.61,36.07) v3(166.21,43.57) v3(166.17,41.05) v3(166.25,46.1) v3(166.25,45.29) v3(167.07,46.1) v3(167.07,45.29) v3(167.51,31.62) v3(167.51,30.61) v3(168.5,1.3) v3(171.58,30.61) v3(172.42,1.3) v3(174,46.74) v3(174.81,46.74) v3(175.13,37.21) v3(175.13,36.07) v3(175.62,46.74) v3(175.62,45.92) v3(176.45,1.3) v3(177.29,31.62) v3(177.29,30.61) v3(178.82,3.17) v3(180.09,1.3) v3(181.1,30.61) v3(182.75,3.68) v3(182.88,7.11) v3(184.15,1.3) v3(185.14,43.33) v3(186.56,3.3) v3(186.69,7.11) v3(187.2,18.16) v3(187.53,41.01) v3(188.49,1.3) v3(190.12,18.03) v3(191.64,6.99) v3(191.64,2.79) v3(191.96,41) v3(192.41,18.03) v3(192.79,21.46) v3(193.04,29.46) v3(193.93,18.03) v3(194.15,1.3) v3(195.07,21.46) v3(195.33,31.62) v3(196.47,18.03) v3(196.85,35.81) v3(197.1,7.49) v3(197.23,2.92) v3(197.99,21.46) v3(198.18,40.9) v3(198.88,32.77) v3(199.14,18.16) v3(199.14,1.28) v3(199.77,43.81) v3(199.86,48.9) v3(200,53.6) v3(200.41,21.46) v3(200.91,29.97) v3(201.55,18.03) v3(201.98,46.06) v3(202.5,51.18) v3(205.56,53.6) v3(207.32,50.86) v3(208.83,17.45) v3(209.65,17.45) v3(210.48,53.64) v3(211.76,27.7) v3(212.56,50.96) v3(212.65,27.7) v3(213.54,27.7) v3(214.38,7.11) v3(214.63,33.15) v3(215.28,53.62) v3(215.48,1.3) v3(215.93,20.57) v3(216.66,35.81) v3(216.81,20.57) v3(217.29,43.03) v3(217.44,51.36) v3(217.65,47.75) v3(217.68,3.81) v3(217.81,20.57) v3(218.34,25.88) v3(218.44,36.32) v3(218.69,20.57) v3(219.07,1.3) v3(219.61,25.88) v3(219.58,20.57) v3(220.26,53.62) v3(220.54,49.8) v3(220.53,45.53) v3(220.51,41.73) v3(221.49,31.75) v3(221.62,6.99) v3(222.04,40.99) v3(223.27,1.3) v3(225.98,40.98) v3(226.19,3.17) v3(227.24,1.3) v3(227.71,27.43) v3(228.35,36.2) v3(228.35,32.38) v3(229.24,36.2) v3(229.24,32.38) v3(229.36,24.13) v3(229.87,27.56) v3(230.49,40.99) v3(230.84,1.42) v3(230.89,5.08) v3(231.52,25.91) v3(233.81,38.35) v3(234.34,40.99) v3(234.76,1.36) v3(235.11,43.57) v3(235.15,46.1) v3(235.15,45.29) v3(235.84,5.59) v3(235.97,46.1) v3(235.97,45.29) v3(238.43,1.3) v3(239.4,2.79) v3(241.17,41.02) v3(241.17,40.13) v3(241.17,38.86) v3(242.06,5.46) v3(242.9,46.74) v3(243.46,34.29) v3(243.46,33.4) v3(243.5,1.3) v3(243.71,46.74) v3(244.52,46.74) v3(244.52,45.92) v3(245.24,5.84) v3(245.87,2.79) v3(247.27,33.4) v3(247.56,1.3) v3(248.54,7.49) v3(250.06,25.02) v3(250.32,22.99) v3(250.32,4.45) v3(252.6,7.11) v3(252.6,2.79) v3(254.02,43.48) v3(254.13,26.42) v3(254.38,9.02) v3(255.02,22.99) v3(255.02,4.7) v3(255.4,25.27) v3(255.5,1.32) v3(256.29,29.46) v3(257,2.28) v3(257.06,40.99) v3(257.43,25.02) v3(258.57,31.88) v3(258.95,23.88) v3(259.21,5.08) v3(259.46,33.66) v3(259.52,1.34) v3(259.59,27.81) v3(260.16,40.84) v3(260.6,7.87) v3(261.37,39.5) v3(262.13,36.07) v3(262.58,1.3) v3(263.14,27.81) v3(264.03,23.24) v3(264.1,40.92) v3(264.8,4.45) v3(265.68,39.37) v3(265.81,7.49) v3(266.06,31.75) v3(266.19,26.42) v3(266.46,1.28) v3(267.5,40.92) v3(268.35,3.68) v3(269.11,25.15) v3(269.24,28.32) v3(269.75,46.74) v3(269.75,43.43) v3(270.62,1.3) v3(271.14,51.18) v3(271.54,53.56) v3(272.42,35.05) v3(273.56,40.77) v3(274.66,1.32) v3(275.64,53.58) v3(276.48,39.5) v3(277.11,8.76) v3(277.88,1.3) v3(278.13,42.04) v3(278.26,3.94) v3(278.76,34.92) v3(279.6,53.6) v3(281.69,40.13) v3(281.98,1.3) v3(282.07,8.38) v3(282.57,51.44) v3(283.59,25.15) v3(283.97,1.3) v3(284.1,48.56) v3(284.08,43.02) v3(284.23,53.7) v3(284.23,28.7) v3(284.35,4.45) v3(284.86,37.85) v3(285.12,35.18) v3(286,31.5) v3(286.13,8.13) v3(287.27,46.86) v3(287.91,39.5) v3(288.42,28.57) v3(289.43,51.44) v3(289.43,48.77) v3(289.43,45.34) v3(289.43,41.91) v3(289.43,1.3) v3(290.58,24.89) v3(290.58,4.45) v3(290.96,8.51) v3(291.85,41) v3(293.24,39.37) v3(294.13,1.3) v3(294.26,24.51) v3(294.89,41) v3(294.89,32.26) v3(295.27,4.57) v3(295.4,37.21) v3(295.53,27.69) v3(297.94,41) v3(299.21,6.22) v3(299.85,1.3) v3(299.97,18.92) v3(300.46,36.91) v3(300.46,36.07) v3(300.46,34.74) v3(300.46,33.91) v3(300.61,41) v3(303.4,18.29) v3(303.91,41.02) v3(304.04,46.1) v3(304.04,45.21) v3(304.04,43.69) v3(304.04,4.19) v3(304.85,46.08) v3(304.93,45.21) v3(305.31,1.3) v3(306.45,6.48) v3(307.98,18.29) v3(309.63,36.32) v3(309.63,35.31) v3(309.63,34.16) v3(309.63,33.15) v3(311.02,3.68) v3(311.53,1.3) v3(311.91,46.74) v3(312.55,45.85) v3(313.18,46.74) v3(313.42,45.96) v3(313.82,18.29) v3(314.07,6.22) v3(318.64,1.3) v3(318.77,4.45) v3(322.07,17.14) v3(322.58,6.22) v3(322.94,45.59) v3(322.94,42.55) v3(322.96,22.86) v3(323.47,41.02) v3(323.85,18.41) v3(324.36,26.16) v3(325.25,1.3) v3(326.52,41.02) v3(326.52,39.24) v3(327.66,3.17) v3(328.04,36.45) v3(328.04,30.35) v3(329.31,32.89) v3(329.44,41.02) v3(329.95,6.6) v3(330.2,17.91) v3(331.85,39.24) v3(331.98,1.3) v3(332.36,35.31) v3(332.74,3.81) v3(332.99,41.02) v3(334.39,18.16) v3(334.77,30.61) v3(335.41,22.99) v3(335.66,8.76) v3(336.55,41.02) v3(337.49,52.2) v3(337.49,49.15) v3(337.49,45.59) v3(337.49,42.55) v3(338.71,1.3) v3(338.84,49.78) v3(338.84,44.32) v3(338.96,53.72) v3(338.96,42.8) v3(339.09,9.14) v3(339.22,24.77) v3(339.34,32.38) v3(339.34,28.07) v3(340.23,52.32) v3(342.26,53.72) v3(342.77,50.67) v3(343.28,16) v3(345.06,13.97) v3(345.31,53.72) v3(345.69,51.94) v3(345.95,28.07) v3(345.95,24.51) v3(346.07,31.88) v3(346.84,50.55) v3(348.23,53.72) v3(348.36,15.88) v3(350.39,13.84) v3(351.03,52.45) v3(351.15,24.26) v3(351.28,33.15) v3(351.41,8.76) v3(351.92,26.42) v3(352.17,53.72) v3(352.55,50.67) v3(353.31,16.76) v3(353.44,1.3) v3(354.2,13.84) v3(354.71,47.5) v3(354.71,5.59) v3(354.96,42.29) v3(354.96,8.51) v3(355.09,39.62) v3(355.47,53.72) v3(355.98,3.3) v3(356.11,50.29) v3(356.62,44.32) v3(357.25,25.02) v3(357.25,1.3) v3(357.38,28.19) v3(357.5,39.5) v3(357.5,23.24) v3(357.63,30.86) v3(358.36,53.67) v3(358.36,50.07) v3(358.36,47.37) v3(358.36,44.96) v3(358.36,42.8) v3(358.78,41.02) v3(359.28,34.92) v3(359.41,3.3) v3(361.31,36.58) v3(361.7,1.3) v3(361.95,41.02) v3(361.95,32.64) v3(362.97,37.72) v3(363.86,35.05) v3(364.74,41) v3(365,37.85) v3(365.25,33.78) v3(367.03,1.3) v3(367.79,41.02) v3(369.14,37.57) v3(369.13,36.75) v3(369.11,35.13) v3(369.16,35.94) v3(369.83,41.02) v3(369.95,1.3) v3(371.6,1.3) v3(371.73,41.02) v3(372.92,46.58) v3(372.95,45.77) v3(372.9,44.96) v3(372.9,42.04) v3(373.38,1.3) v3(373.74,46.69) v3(373.76,45.77) v3(373.76,44.96) v3(375.16,1.35) v3(378.16,41.27) v3(378.33,39.78) v3(378.71,40.5) v3(378.94,37.47) v3(379.6,1.3) v3(379.98,36.55) v3(379.98,35.74) v3(380.75,46.81) v3(380.75,45.99) v3(380.75,4.03) v3(381.56,46.79) v3(381.58,45.97) v3(381.56,4.06) v3(382.3,46.35) v3(382.36,45.54) v3(382.43,4.03) v3(384.68,1.3) v3(388.11,1.3) v3(390.91,1.32) v3(391.85,46.48) v3(391.8,45.09) v3(391.8,42.67) v3(392.81,40.89) v3(394.72,3.68) v3(394.72,1.32) v3(394.97,40.89) v3(396.75,3.05) v3(396.88,40.89) v3(396.88,4.95) v3(398.02,1.4) v3(398.78,7.37) v3(399.16,38.99) v3(399.8,40.89) v3(400.69,5.97) v3(402.46,40.89) v3(402.46,3.05) v3(402.72,7.49) v3(402.97,1.4) v3(403.48,38.99) v3(404.75,5.97) v3(405,40.89) v3(405,21.72) v3(406.02,52.7) v3(406.02,50.42) v3(406.02,48.64) v3(406.02,46.86) v3(406.02,45.21) v3(406.02,43.31) v3(406.02,41.91) v3(406.4,1.4) v3(407.29,7.49) v3(407.54,53.59) v3(407.54,3.05) v3(407.8,21.72) v3(408.05,48.26) v3(408.05,39.24) v3(408.05,16) v3(408.43,43.31) v3(408.43,18.92) v3(408.43,9.78) v3(409.19,1.4) v3(409.32,51.05) v3(409.57,7.37) v3(409.96,20.7) v3(410.46,53.59) v3(410.46,27.05) v3(410.59,32.38) v3(410.85,15.88) v3(410.85,9.78) v3(411.23,29.97) v3(411.23,3.05) v3(411.35,18.29) v3(412.12,44.7) v3(412.37,1.4) v3(412.62,24.51) v3(412.62,7.37) v3(413.13,51.56) v3(413.13,41.78) v3(413.51,9.78) v3(413.64,15.62) v3(414.02,53.59) v3(414.15,36.07) v3(414.91,22.73) v3(414.91,1.4) v3(415.42,45.09) v3(415.8,8) v3(416.31,11.18) v3(416.56,39.24) v3(416.81,16.89) v3(416.94,51.94) v3(417.07,53.59) v3(417.83,34.92) v3(418.08,8.26) v3(418.21,31.62) v3(418.34,4.95) v3(418.46,23.24) v3(418.72,1.4) v3(418.97,3.3) v3(419.48,42.04) v3(419.61,10.92) v3(419.74,53.59) v3(419.74,17.14) v3(419.86,27.3) v3(421.26,51.44) v3(421.26,1.4) v3(421.39,48.77) v3(421.39,46.35) v3(421.39,42.93) v3(421.39,39.88) v3(421.39,36.58) v3(421.39,31.88) v3(421.39,28.83) v3(421.39,24.89) v3(421.39,21.59) v3(421.39,18.54) v3(421.39,15.24) v3(421.39,11.3) v3(421.39,8.26) v3(421.39,4.57)
